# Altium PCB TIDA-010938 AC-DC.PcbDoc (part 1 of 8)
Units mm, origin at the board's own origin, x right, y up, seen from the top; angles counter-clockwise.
Board outline 280 x 180.15 mm, 4 copper layers (Top Layer, Layer 1, Layer 2, Bottom Layer), stack 1.787 mm thick; 723 components, 427 nets, 2244 pads, 2295 vias.
Unrouted connection lines stored in the file: 17.
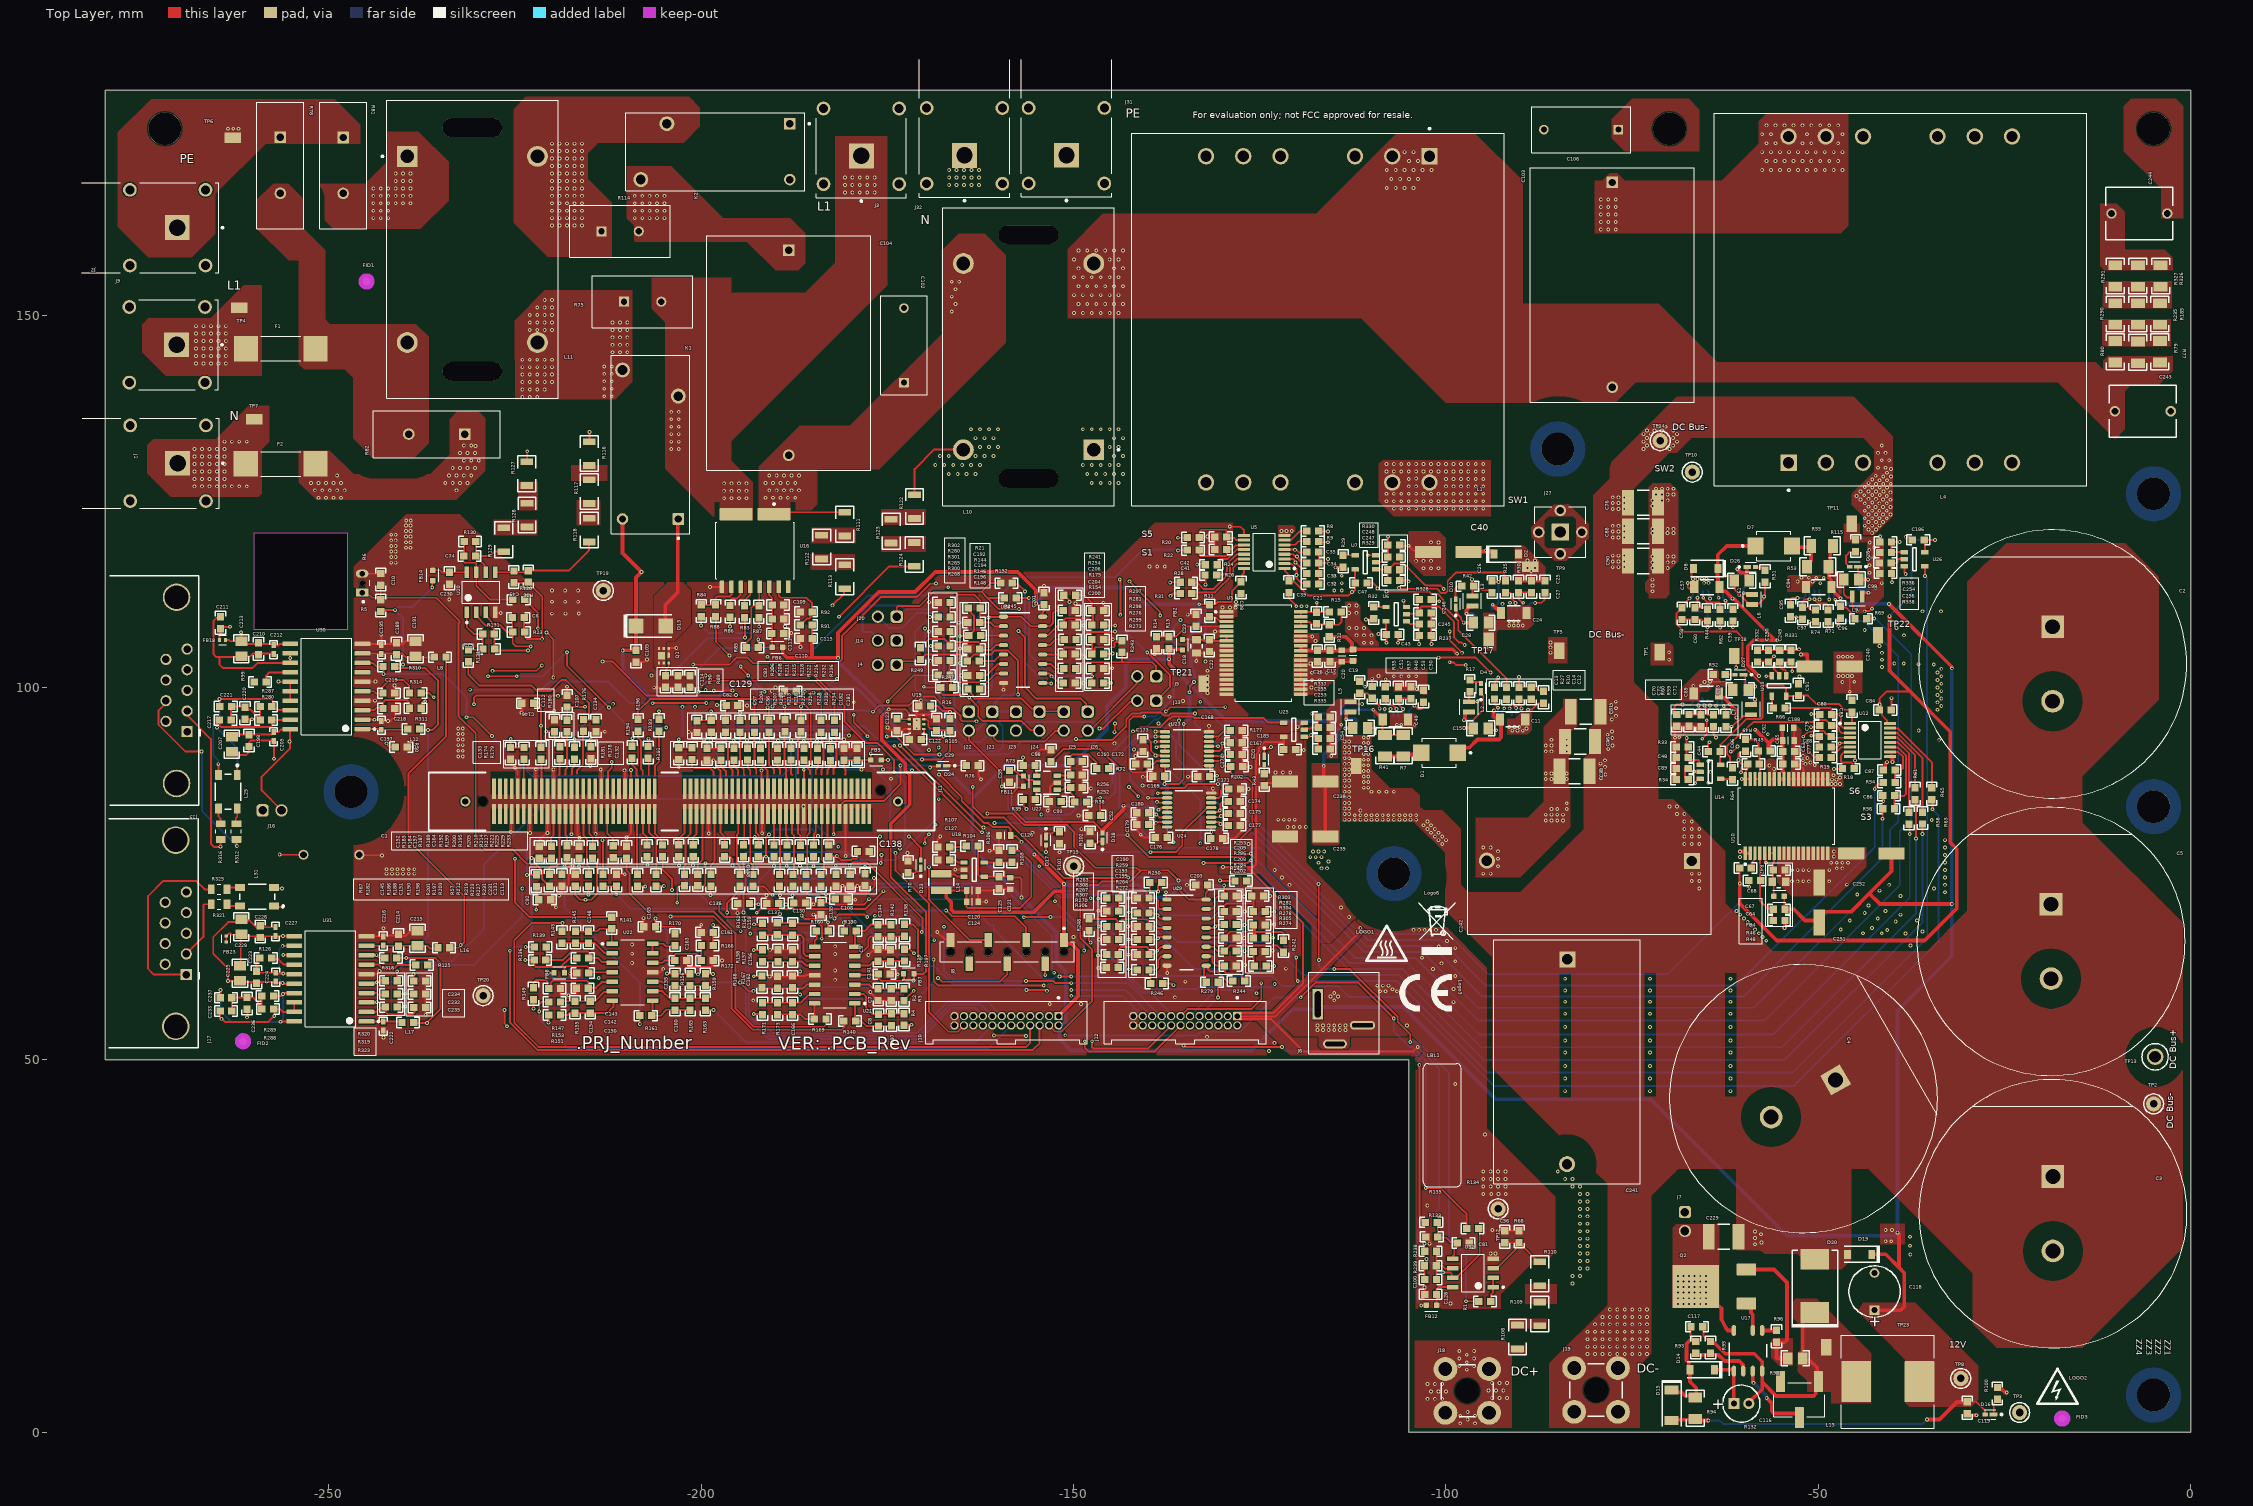
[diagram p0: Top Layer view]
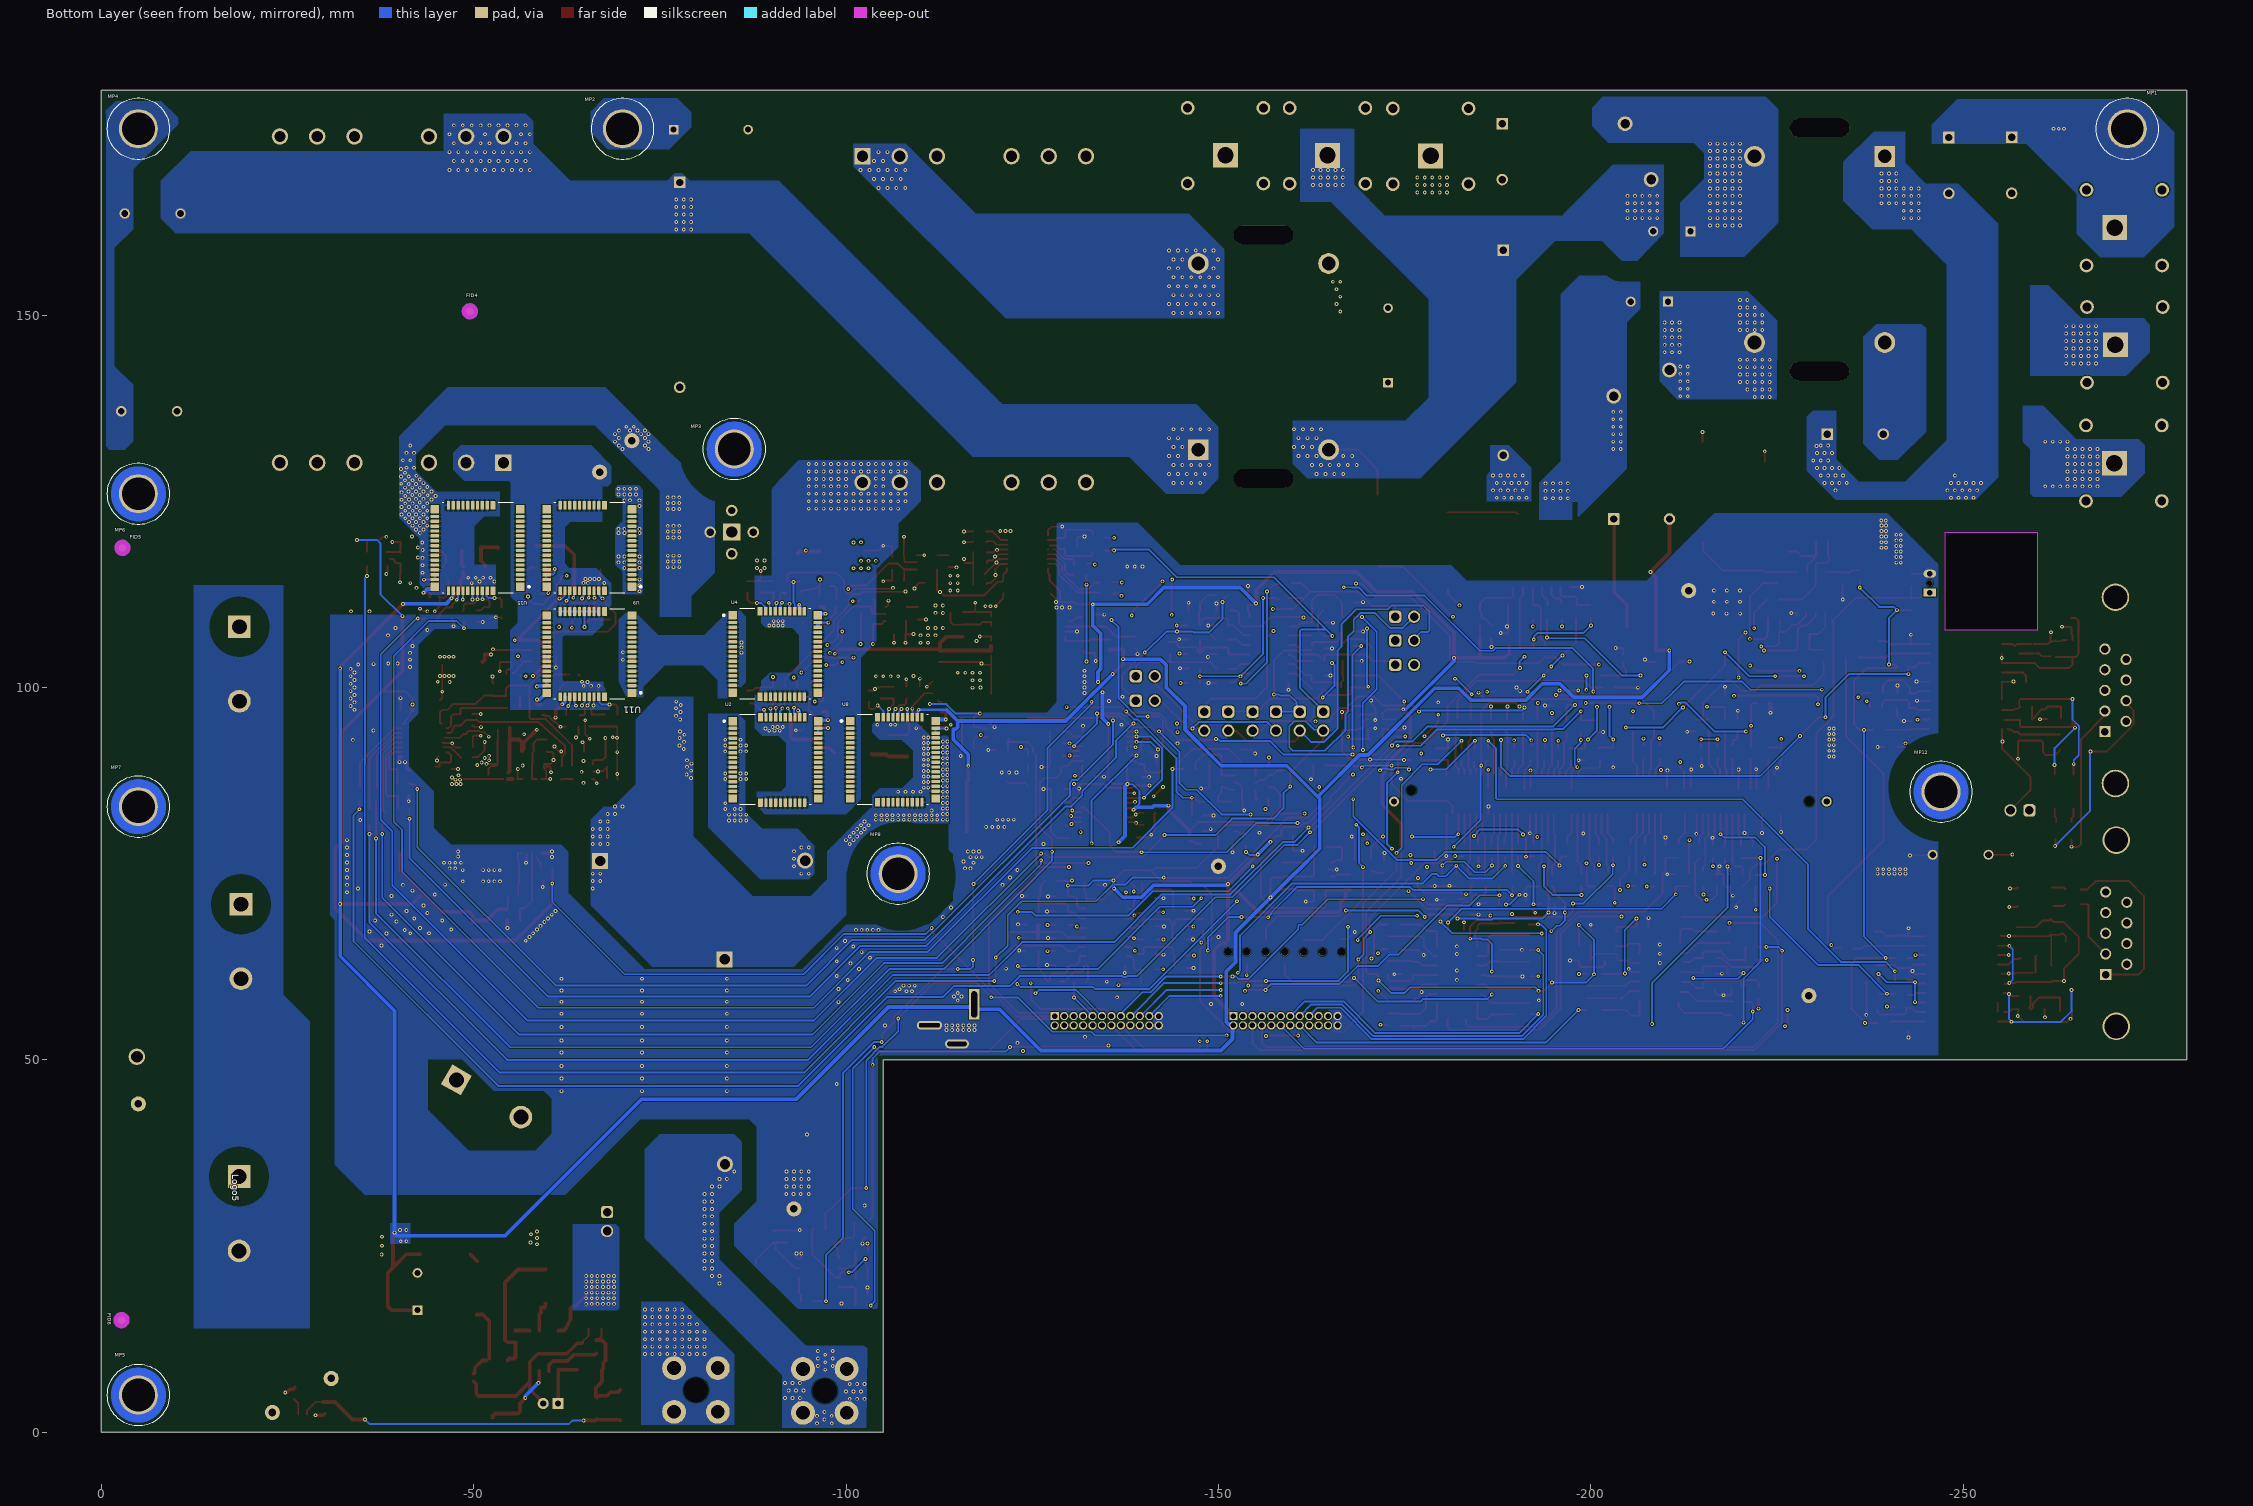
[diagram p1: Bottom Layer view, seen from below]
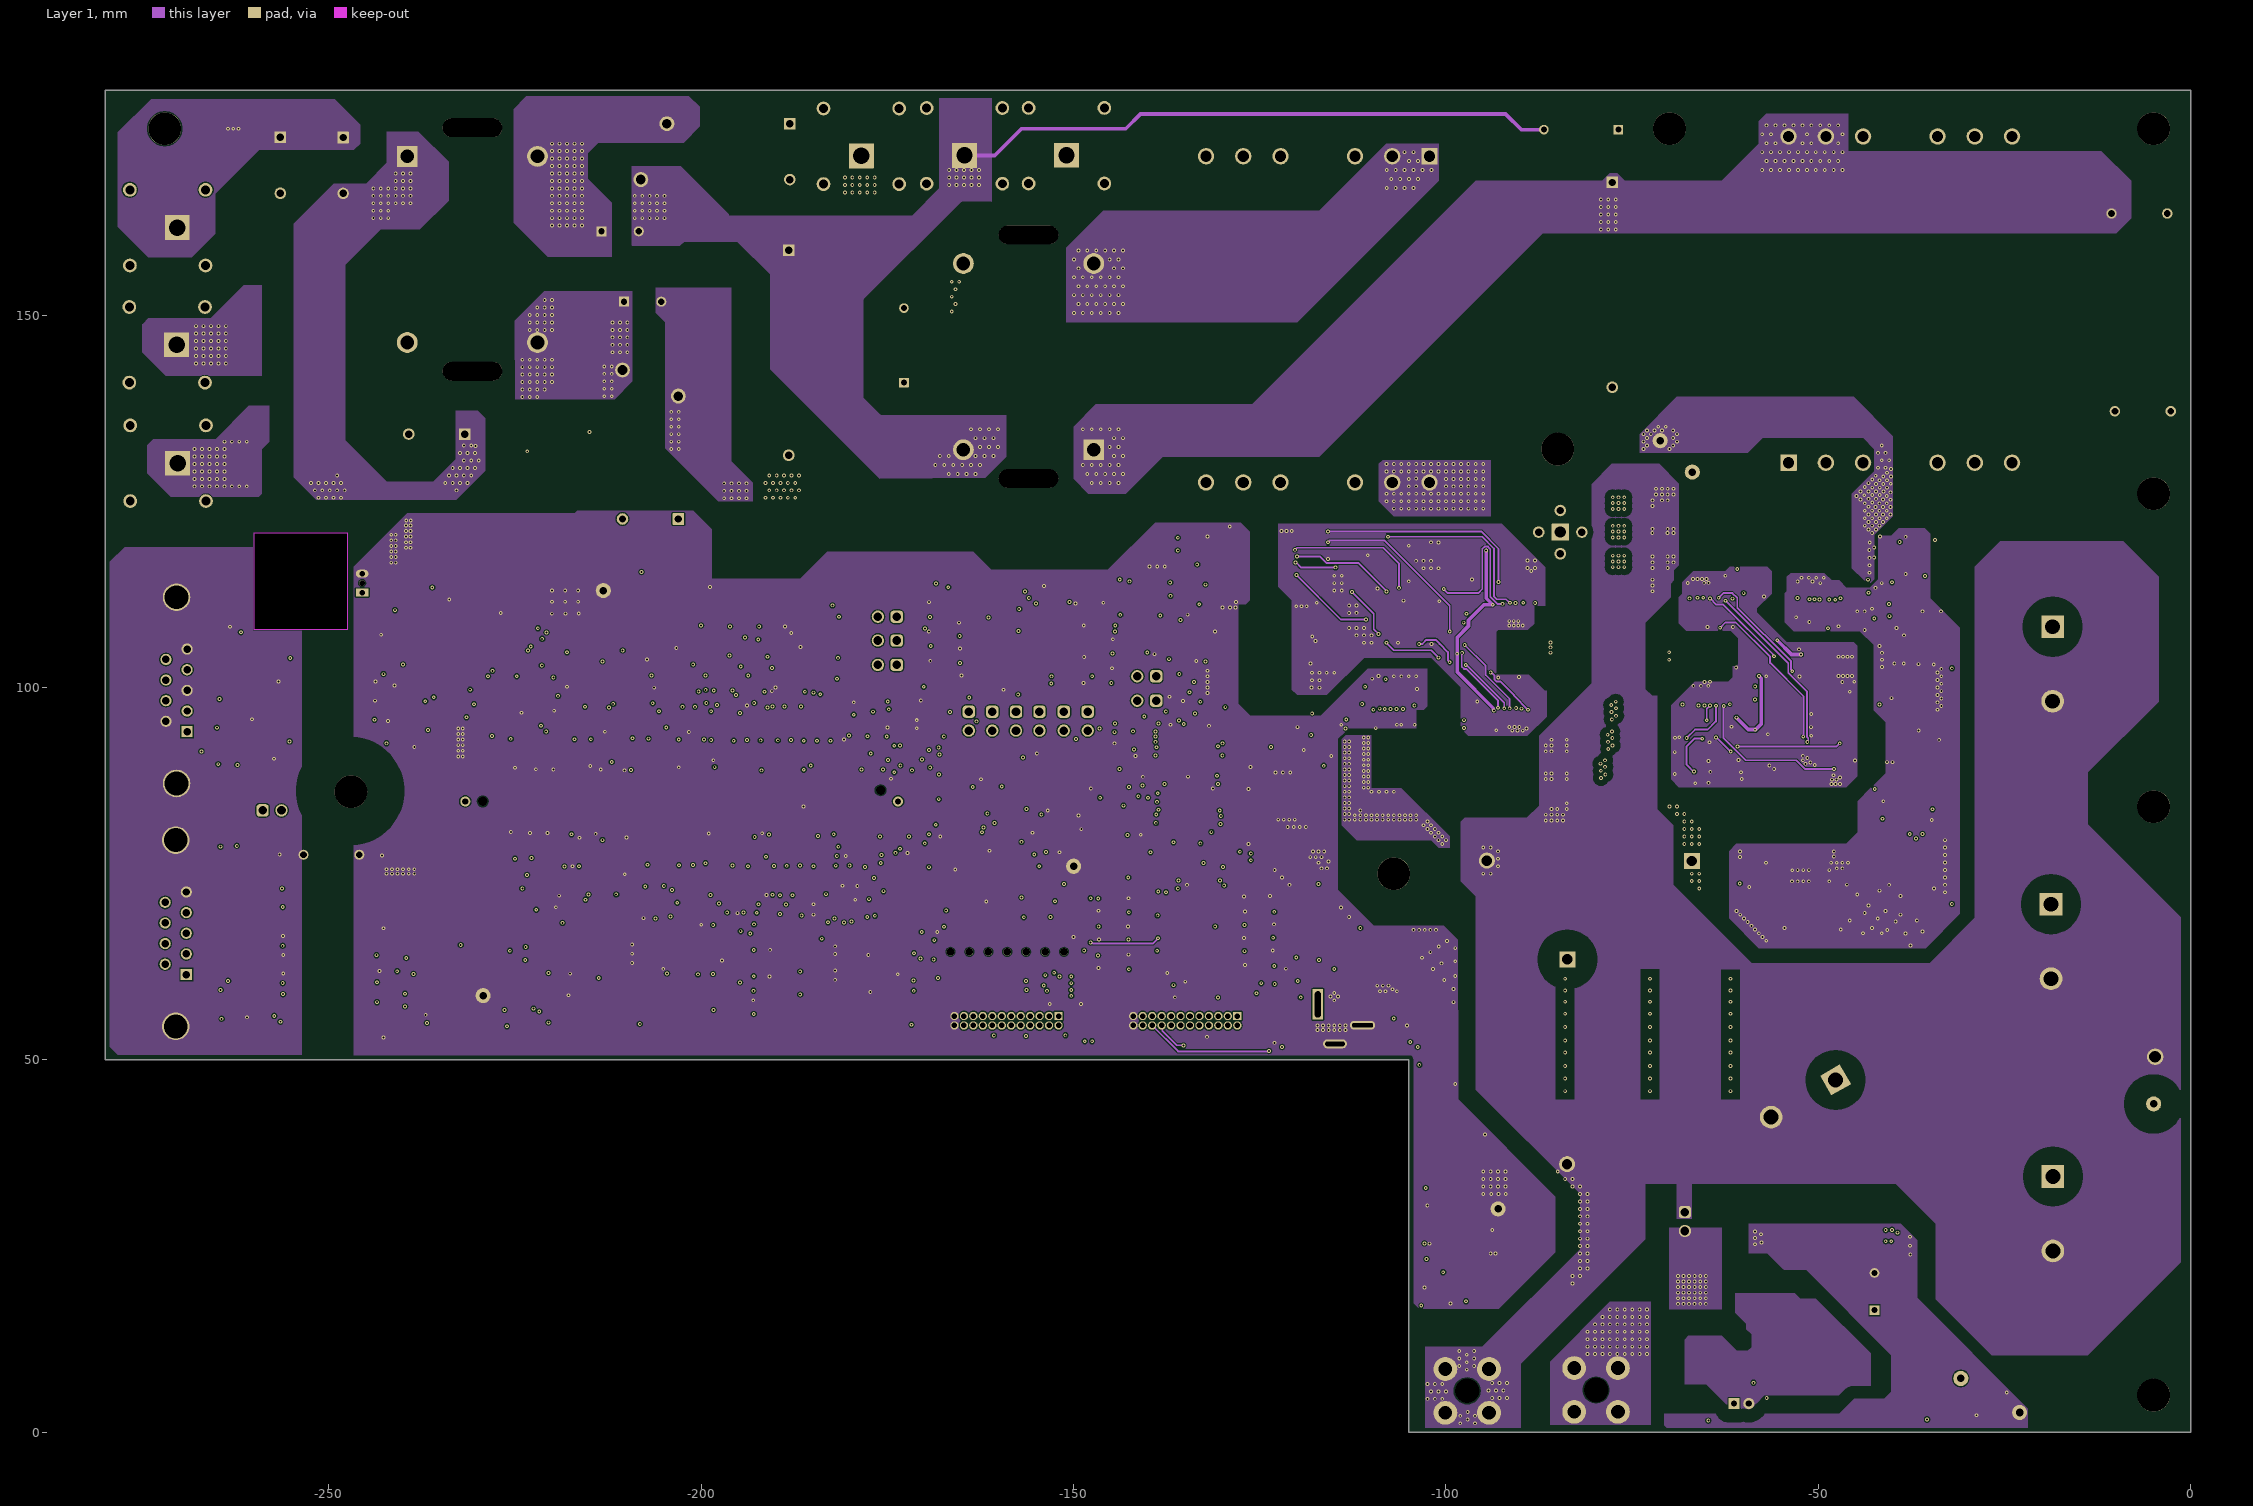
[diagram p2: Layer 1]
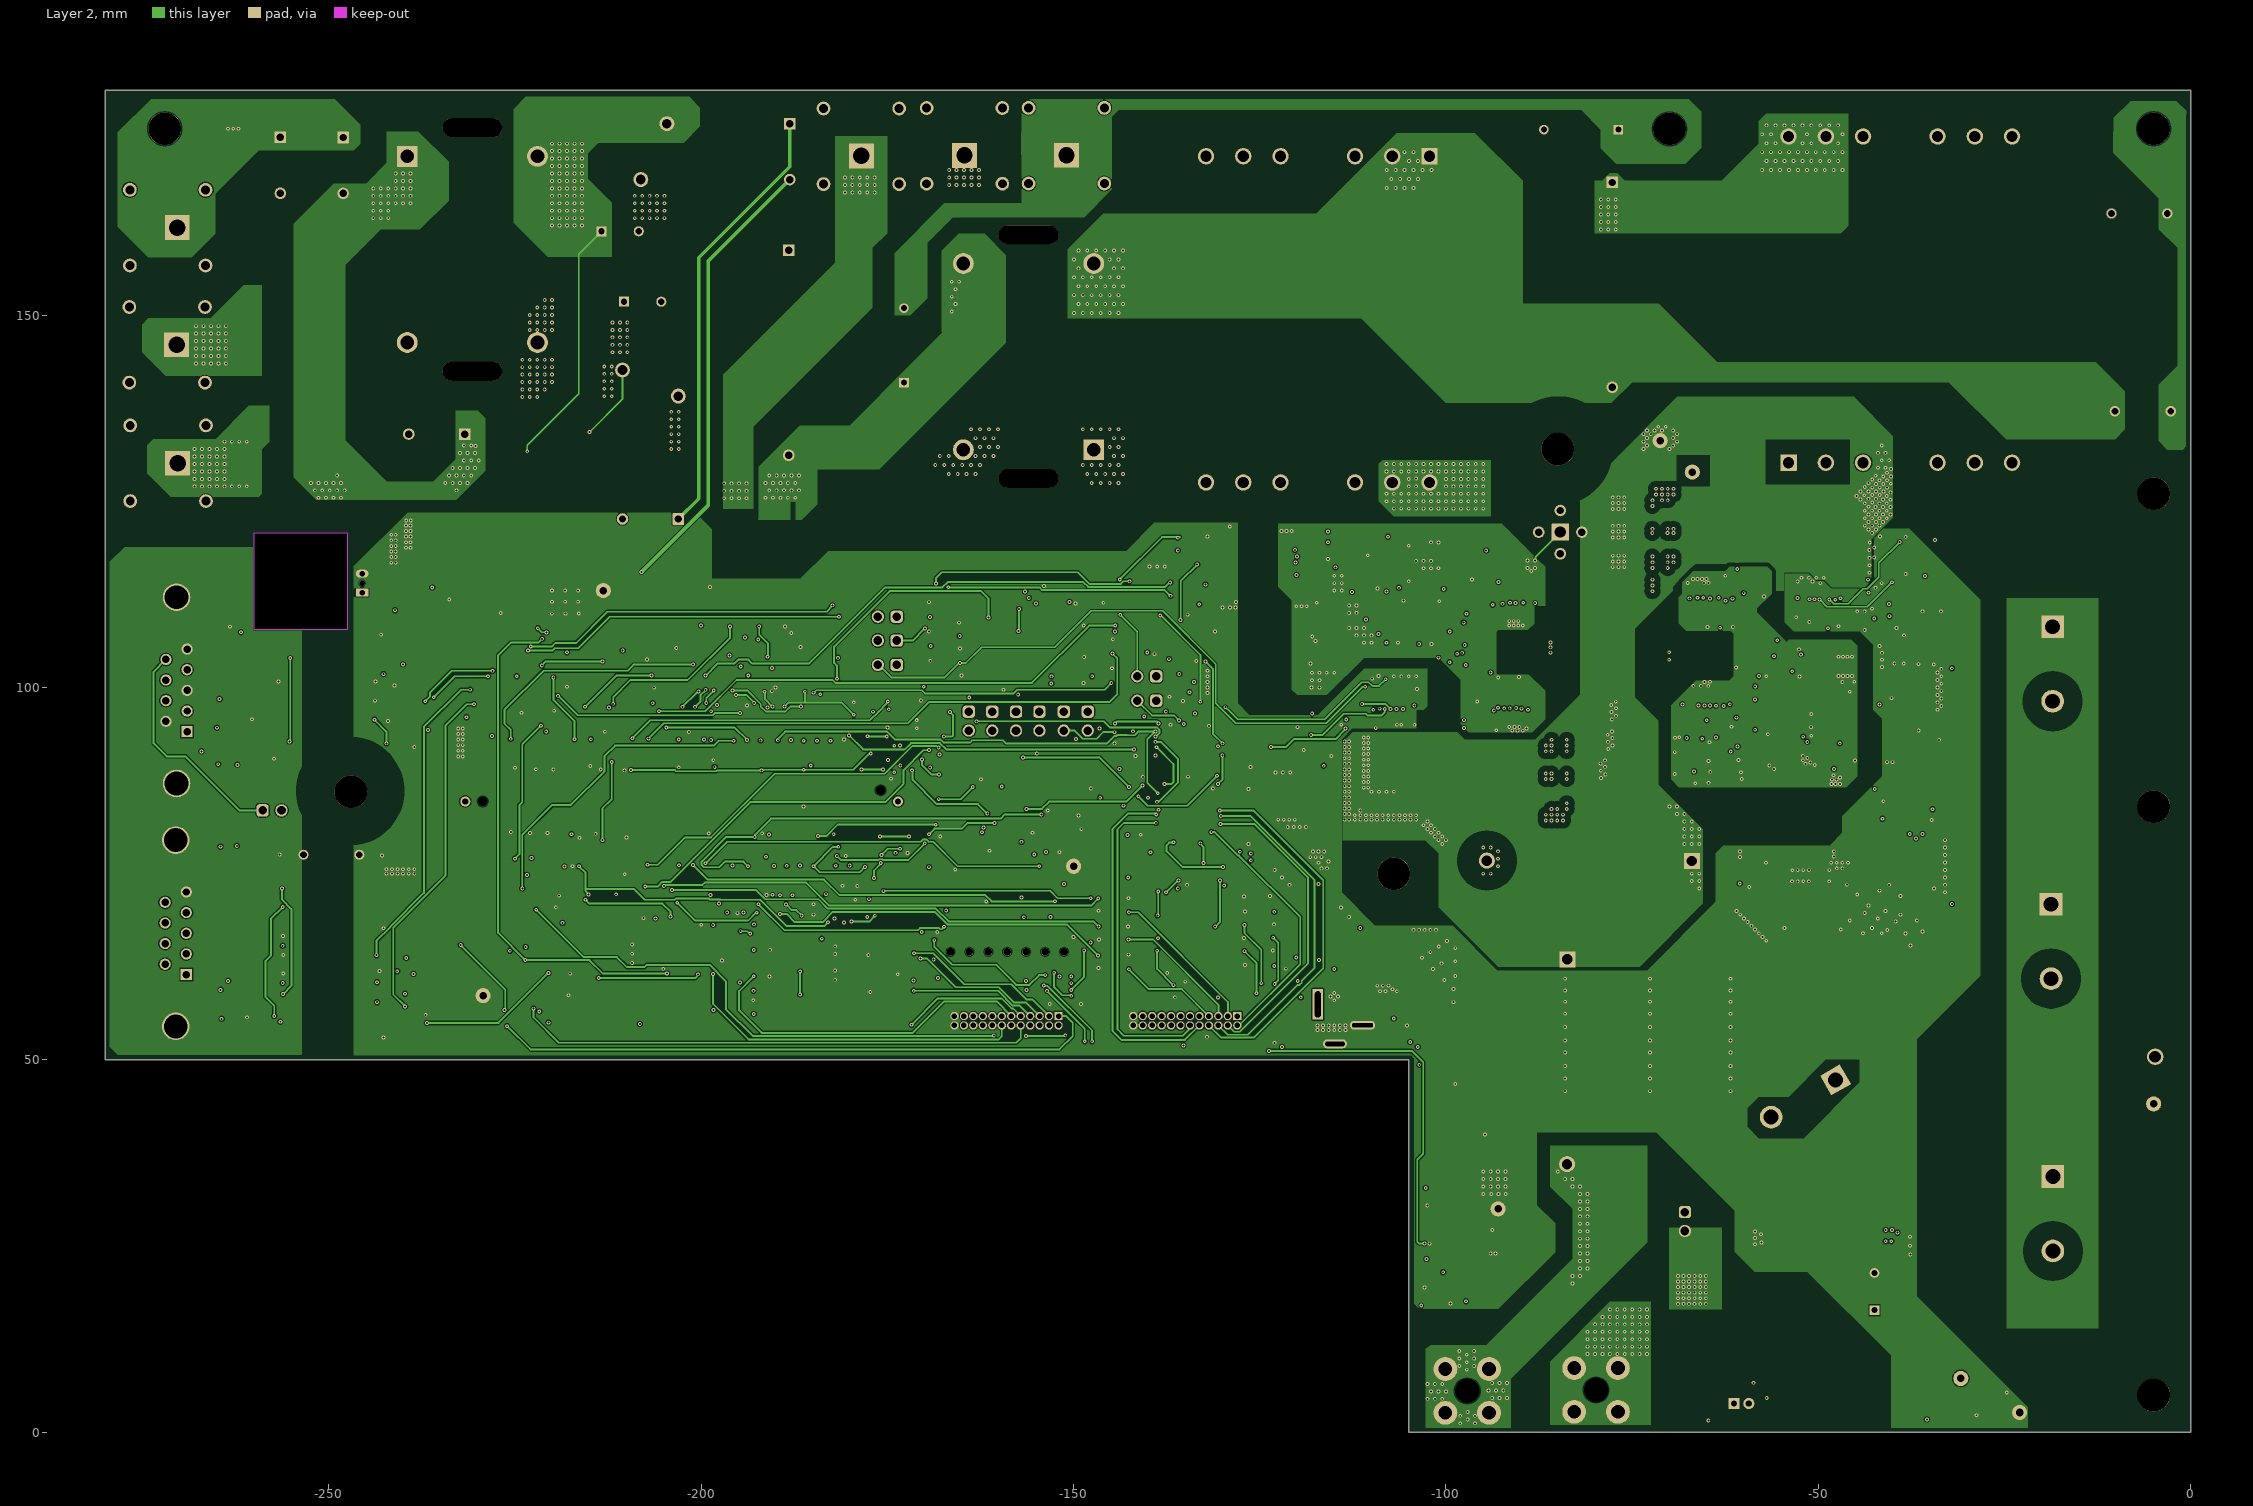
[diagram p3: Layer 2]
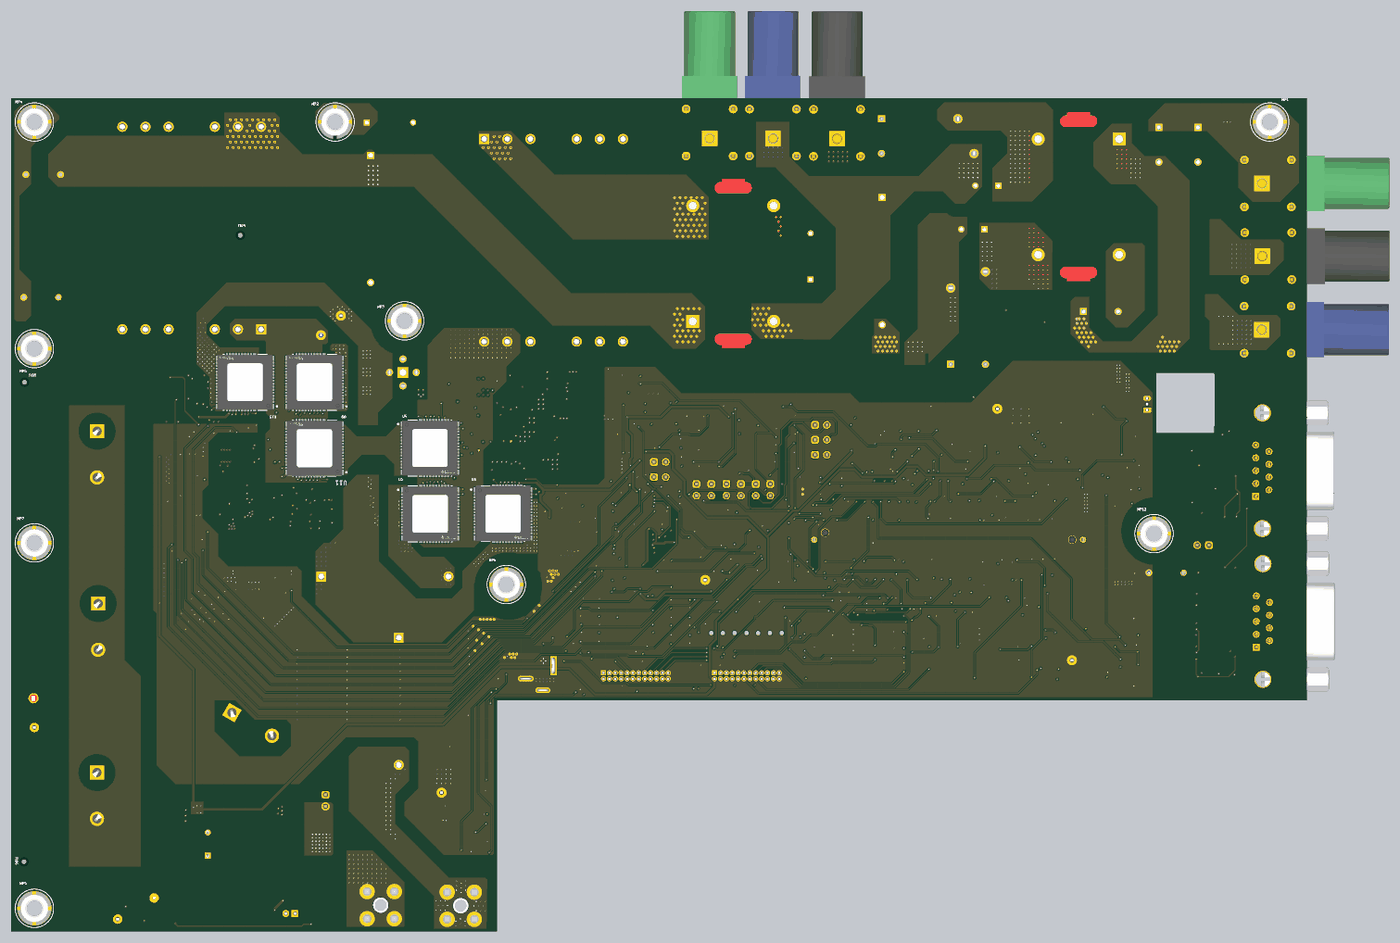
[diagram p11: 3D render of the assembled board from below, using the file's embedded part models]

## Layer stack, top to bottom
Top Solder: solder mask 0.0102, Solder Resist, Dk 3.5
Top Layer: signal copper 0.0356
Dielectric 1: prepreg 0.0711, PP-006, Dk 4.1
Layer 1: signal copper 0.035
Dielectric1: core 1.5037, FR-4 High Tg, Dk 4.8
Layer 2: signal copper 0.035
Dielectric 2: prepreg 0.0711, PP-006, Dk 4.1
Bottom Layer: signal copper 0.0356
Bottom Solder: solder mask 0.0102, Solder Resist, Dk 3.5

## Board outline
-105,0 0,0 0,180.15 -280,180.15 -280,50 -105,50
cut-out: -247.5,120.75 -247.5,107.75 -260,107.75 -260,120.75

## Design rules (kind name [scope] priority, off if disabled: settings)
AcuteAngle [All] p1: minimum=4.50000000000000E+0001 checktracksonly=FALSE
AssemblyTestPointUsage [All] p1: valid=2
BoardOutlineClearance BoardOutlineClearance_MountingHoles [OnCopper and InComponentClass('Mounting Holes')] p1: gap=1 ignorepadtopadclearanceinfootprint=FALSE
BoardOutlineClearance BoardOutlineClearance_Poly [OnCopper and IsPoly] p2: gap=0.635 ignorepadtopadclearanceinfootprint=FALSE
BoardOutlineClearance [OnCopper and Not InComponentClass('Logo') and not InComponentClass('FiducialMark') and not InRegion(1000,500,4000,800) and not InPoly] p3: gap=1.016 ignorepadtopadclearanceinfootprint=FALSE
Clearance PE_PELV [InNetClass('PE') vs InNetClass('PELV')] p1: gap=2 ignorepadtopadclearanceinfootprint=FALSE
Clearance BUCK [InNetClass('HVP')   OR InNetClass('HVN') vs InNetClass('Buck')] p2: gap=1.8 ignorepadtopadclearanceinfootprint=FALSE
Clearance SW1 [(InNetClass('HVN')) OR (InNetClass('HVP')) vs InNetClass('HV_SW_Node1')] p3: gap=0.6 ignorepadtopadclearanceinfootprint=FALSE
Clearance SW2 [(InNetClass('HVN')) OR (InNetClass('HVP')) vs InNetClass('HV_SW_Node2')] p4: gap=0.6 ignorepadtopadclearanceinfootprint=FALSE
Clearance SWMID [((InNetClass('HV_SW_Node1')) OR (InNetClass('HV_SW_Node2'))) vs InNetClass('HV_SW_Mid')] p5: gap=2.1 ignorepadtopadclearanceinfootprint=FALSE
Clearance ACL_ACN [InNetClass('ACL') vs InNetClass('ACN')] p6: gap=2.8 ignorepadtopadclearanceinfootprint=FALSE
Clearance PE [InNetClass('PE') vs InNetClass('All Nets')] p7 off: gap=2.5 ignorepadtopadclearanceinfootprint=FALSE
Clearance PELV [InNetClass('PELV')] p8 off: gap=6 ignorepadtopadclearanceinfootprint=FALSE
Clearance HVN_HVP [InNetClass('HVN') vs InNetClass('HVP')] p9: gap=0.8 ignorepadtopadclearanceinfootprint=FALSE
Clearance Minimum_Distance [All] p10: gap=0.15 ignorepadtopadclearanceinfootprint=FALSE
Clearance Clearance_Keepouts [((IsTrack Or IsArc) And Not InPoly) And IsFree and IsKeepOut vs ((IsTrack Or IsArc) And Not InPoly) And IsFree and IsKeepOut] p11 off: gap=0 ignorepadtopadclearanceinfootprint=FALSE
Clearance Clearance_Poly [InPolygon] p12: gap=0.254 ignorepadtopadclearanceinfootprint=TRUE
Clearance Clearance_FiducialMark [IsKeepOut and InComponentClass('FiducialMark') vs IsPad and InComponentClass('FiducialMark')] p13: gap=0 ignorepadtopadclearanceinfootprint=FALSE
ComponentClearance ComponentClearance_MountingHoles_FiducialMarks [InComponentClass('Mounting Holes') vs InComponentClass('FiducialMark')] p1: gap=1.27 collisioncheckmode=3 verticalgap=0.254 showdistances=FALSE
ComponentClearance ComponentClearance_Shunt [InComponentClass('Header') vs InComponentClass('Shunt')] p2: gap=0 collisioncheckmode=3 verticalgap=0 showdistances=FALSE
ComponentClearance ComponentClearance_Logo [InComponentClass('Logo')] p3: gap=0.762 collisioncheckmode=3 verticalgap=0.254 showdistances=FALSE
ComponentClearance ComponentClearance_ScrewToNut [(HasFootprint('NY PMS 440 0025 PH')) vs (HasFootprint('Keystone_1902C'))] p4: gap=0.127 collisioncheckmode=3 verticalgap=0.254 showdistances=FALSE
ComponentClearance ComponentClearance_MountingHoles [InComponentClass('Mounting Holes')] p5: gap=2.54 collisioncheckmode=3 verticalgap=2540 showdistances=FALSE
ComponentClearance ComponentClearance_SmallPassives [HasFootprint('0201*') or HasFootprint('0402*') or HasFootprint('0508') or HasFootprint('0603*') or HasFootprint('0612') or HasFootprint('0805*') or HasFootprint('0815*') or HasFootprint('0830*') or HasFootprint('1206*') or HasFootprint('1210*') or HasFootprint('1808*') or HasFootprint('1812*') or HasFootprint('1825*') or HasFootprint('2010*') or HasFootprint('2220*') or HasFootprint('2225*') or HasFootprint('2512*') or HasFootprint('2728*') or HasFootprint('3518*') vs HasFootprint('0201*') or HasFootprint('0402*') or HasFootprint('0508') or HasFootprint('0603*') or HasFootprint('0612') or HasFootprint('0805*') or HasFootprint('0815*') or HasFootprint('0830*') or HasFootprint('1206*') or HasFootprint('1210*') or HasFootprint('1808*') or HasFootprint('1812*') or HasFootprint('1825*') or HasFootprint('2010*') or HasFootprint('2220*') or HasFootprint('2225*') or HasFootprint('2512*') or HasFootprint('2728*') or HasFootprint('3518*')] p6: gap=0.38 collisioncheckmode=3 verticalgap=0.254 showdistances=FALSE
ComponentClearance ComponentClearance_THtoSMT [IsThruComponent vs IsSMTComponent] p7: gap=0.762 collisioncheckmode=3 verticalgap=0.762 showdistances=FALSE
ComponentClearance ComponentClearance_THtoTH [IsThruComponent vs IsThruComponent] p8: gap=0.508 collisioncheckmode=3 verticalgap=0.762 showdistances=FALSE
ComponentClearance [All] p9: gap=0.508 collisioncheckmode=3 verticalgap=0.254 showdistances=FALSE
DiffPairsRouting [All] p1: maxlimit=2.54 minlimit=0.254 mostfreqgap=0.254 toplayer_minwidth=0.381 toplayer_maxwidth=0.381 toplayer_prefwidth=0.381 midlayer1_minwidth=0.381 midlayer1_maxwidth=0.381 midlayer1_prefwidth=0.381 midlayer2_minwidth=0.381 midlayer2_maxwidth=0.381 midlayer2_prefwidth=0.381 bottomlayer_minwidth=0.381 bottomlayer_maxwidth=0.381 bottomlayer_prefwidth=0.381 maxuncoupledlength=25.4
FabricationTestPointUsage TestPointUsage [All] p1: valid=2 allowmultiple=FALSE
FabricationTestpoint Testpoint [All] p1: side=3 testpointundercomponent=TRUE minsize=1.016 maxsize=2.54 preferedsize=1.524 minholesize=0 maxholesize=1.016 preferedholesize=0.813 testpointgrid=0.025 allowsidetop=TRUE allowsidebottom=TRUE usegrid=TRUE gridtolerance=0
FanoutControl Fanout_LCC [IsLCC] p1: bgadir=Out bgaviamode=Centered fanoutstyle=Auto fanoutdirection=Alternating viagrid=0.025 // Fanout_LCC (Default Rule)
FanoutControl Fanout_BGA [IsBGA] p2: bgadir=Out bgaviamode=Centered fanoutstyle=Auto fanoutdirection=Alternating viagrid=0.025 // Fanout_BGA (Default Rule)
FanoutControl Fanout_Default [All] p4: bgadir=Out bgaviamode=Centered fanoutstyle=Auto fanoutdirection=Alternating viagrid=0.025 // Fanout_Default (Default Rule)
FanoutControl Fanout_Small [(CompPinCount < 5)] p5: bgadir=Out bgaviamode=Centered fanoutstyle=Auto fanoutdirection=OutThenIn viagrid=0.025 // Fanout_Small (Default Rule)
HoleSize [All] p1: absolutevalues=TRUE maxlimit=6.375 minlimit=0.2 maxpercent=80.000 minpercent=20.000
MinimumAnnularRing MinimumAnnularRing_ThermalPadVias [IsVia and InAnyComponent] p1: minimumring=0.125
MinimumAnnularRing [All] p2: minimumring=0.125
MinimumSolderMaskSliver MinimumSolderMaskSliver_Logo [InComponentClass('Logo') vs InComponentClass('Logo')] p1: minsoldermaskwidth=0.018
MinimumSolderMaskSliver [All] p2: minsoldermaskwidth=0.1
PlaneConnect [All] p1: planeconnectstyle=Relief reliefexpansion=0.254 reliefentries=4 reliefconductorwidth=0.254 reliefairgap=0.254
PolygonConnect "GaN 1" [IsNamedPolygon('Bottom Layer-DC Bus-')] p1: thpad.connectstyle=Direct thpad.reliefconductorwidth=0.254 thpad.reliefentries=4 thpad.polygonreliefangle="90 Angle" thpad.airgapwidth=0.254 smdpad.connectstyle=Relief smdpad.reliefconductorwidth=0.254 smdpad.reliefentries=4 smdpad.polygonreliefangle="90 Angle" smdpad.airgapwidth=0.254 via.connectstyle=Direct via.reliefconductorwidth=0.254 via.reliefentries=4 via.polygonreliefangle="90 Angle" via.airgapwidth=0.254
PolygonConnect "GaN 2" [IsNamedPolygon('Bottom Layer-SW_2')] p2: thpad.connectstyle=Direct thpad.reliefconductorwidth=0.254 thpad.reliefentries=4 thpad.polygonreliefangle="90 Angle" thpad.airgapwidth=0.254 smdpad.connectstyle=Relief smdpad.reliefconductorwidth=0.254 smdpad.reliefentries=4 smdpad.polygonreliefangle="90 Angle" smdpad.airgapwidth=0.254 via.connectstyle=Direct via.reliefconductorwidth=0.254 via.reliefentries=4 via.polygonreliefangle="90 Angle" via.airgapwidth=0.254
PolygonConnect "GaN 3" [IsNamedPolygon('BOTTOM_LAYER_SW_MID_P059')] p3: thpad.connectstyle=Direct thpad.reliefconductorwidth=0.254 thpad.reliefentries=4 thpad.polygonreliefangle="90 Angle" thpad.airgapwidth=0.254 smdpad.connectstyle=Relief smdpad.reliefconductorwidth=0.254 smdpad.reliefentries=4 smdpad.polygonreliefangle="90 Angle" smdpad.airgapwidth=0.254 via.connectstyle=Direct via.reliefconductorwidth=0.254 via.reliefentries=4 via.polygonreliefangle="90 Angle" via.airgapwidth=0.254
PolygonConnect "GaN 4" [IsNamedPolygon('BOTTOM_LAYER_DC_BUS+_P066')] p4: thpad.connectstyle=Direct thpad.reliefconductorwidth=0.254 thpad.reliefentries=4 thpad.polygonreliefangle="90 Angle" thpad.airgapwidth=0.254 smdpad.connectstyle=Relief smdpad.reliefconductorwidth=0.254 smdpad.reliefentries=4 smdpad.polygonreliefangle="90 Angle" smdpad.airgapwidth=0.254 via.connectstyle=Direct via.reliefconductorwidth=0.254 via.reliefentries=4 via.polygonreliefangle="90 Angle" via.airgapwidth=0.254
PolygonConnect "GaN 5" [IsNamedPolygon('Bottom Layer-SW_1')] p5: thpad.connectstyle=Direct thpad.reliefconductorwidth=0.254 thpad.reliefentries=4 thpad.polygonreliefangle="90 Angle" thpad.airgapwidth=0.254 smdpad.connectstyle=Relief smdpad.reliefconductorwidth=0.254 smdpad.reliefentries=4 smdpad.polygonreliefangle="90 Angle" smdpad.airgapwidth=0.254 via.connectstyle=Direct via.reliefconductorwidth=0.254 via.reliefentries=4 via.polygonreliefangle="90 Angle" via.airgapwidth=0.254
PolygonConnect "GaN 6" [IsNamedPolygon('BOTTOM_LAYER_DC_BUS+_P007')] p6: thpad.connectstyle=Direct thpad.reliefconductorwidth=0.254 thpad.reliefentries=4 thpad.polygonreliefangle="90 Angle" thpad.airgapwidth=0.254 smdpad.connectstyle=Relief smdpad.reliefconductorwidth=0.254 smdpad.reliefentries=4 smdpad.polygonreliefangle="90 Angle" smdpad.airgapwidth=0.254 via.connectstyle=Direct via.reliefconductorwidth=0.254 via.reliefentries=4 via.polygonreliefangle="90 Angle" via.airgapwidth=0.254
PolygonConnect "GaN 7" [IsNamedPolygon('BOTTOM_LAYER_DC_BUS-_P082')] p7: thpad.connectstyle=Direct thpad.reliefconductorwidth=0.254 thpad.reliefentries=4 thpad.polygonreliefangle="90 Angle" thpad.airgapwidth=0.254 smdpad.connectstyle=Relief smdpad.reliefconductorwidth=0.254 smdpad.reliefentries=4 smdpad.polygonreliefangle="90 Angle" smdpad.airgapwidth=0.254 via.connectstyle=Direct via.reliefconductorwidth=0.254 via.reliefentries=4 via.polygonreliefangle="90 Angle" via.airgapwidth=0.254
PolygonConnect [All] p8: connectstyle=Direct reliefconductorwidth=0.254 reliefentries=4 polygonreliefangle="90 Angle" airgapwidth=0.254
RoutingVias ThermalPadVias [IsVia and InAnyComponent] p1: holewidth=0.254 width=0.508 viastyle="Through Hole" minholewidth=0.2 minwidth=0.5 maxholewidth=1.016 maxwidth=1.651
RoutingVias [All] p2: holewidth=0.254 width=0.508 viastyle="Through Hole" minholewidth=0.2 minwidth=0.5 maxholewidth=1.016 maxwidth=1.651
SilkToBoardRegionClearance [Not ((IsComment or IsDesignator) And (Hide <> 'False')) and not InRegion(1000,500,4000,800)] p1:
SilkToSilkClearance SilkToSilkClearance_Pb-FreeLogo [(HasFootprint('Pb-Free_Overlay_Medium') OR HasFootprint('Pb-Free_Overlay_Small')) vs (HasFootprint('Pb-Free_Overlay_Medium') OR HasFootprint('Pb-Free_Overlay_Small'))] p1: silktosilkclearance=0
SilkToSilkClearance [All] p2: silktosilkclearance=0.1
SilkToSolderMaskClearance SilkToComponentPadClearance [(IsPad or IsFill or IsRegion) and InAnycomponent] p1: minsilkscreentomaskgap=0.127 clearancetoexposedcopper=TRUE
SilkToSolderMaskClearance "Silk to Solder Mask Opening" [All] p2: minsilkscreentomaskgap=0.1 clearancetoexposedcopper=FALSE
SolderMaskExpansion [All] p1: expansion=0.05 istentingtop=FALSE
UnRoutedNet [All] p1: checkbadconnections=TRUE
Width [All] p1: maxlimit=2.54 minlimit=0.25 preferedwidth=0.5 checkconnectedcopper=TRUE
14 further rules are at their usual default settings.

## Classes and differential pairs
net class LOADN: ACLOAD_N
net class LOADL: ACLOAD_L
net class HVP: "DC Bus+" NetC229_1
net class HV_SW_Mid: SW_mid
net class PE: PE PE2 PE3
net class ACN: AC_N ACLOAD_N NetC103_1 NetF2_1 VAC_N
net class ACL: AC_L ACLOAD_L NetC103_2 NetF1_1 VAC_L VAC_SW+
net class Buck: NetC116_1 NetC116_2 NetC117_1 NetQ2_1 NetQ2_3 NetR93_1 NetR96_1 NetR132_2 NetU17_3
net class HVN: 1V65_REF 3V3_HVN 5V_HVN 12V_HVN Batt_H1 Batt_H1_Buff Batt_H2 Batt_H2_Buff Batt_L1 Batt_L1_Buff Batt_L2 Batt_L2_Buff Boost_S1 Boost_S1_Buff Boost_S2 Boost_S2_Buff CAN_RX CAN_TX CS_Batt1 CS_Batt1+ CS_Batt1- CS_Batt2 CS_Batt2+ CS_Batt2- CS_Boost1 CS_Boost1+ CS_Boost1- CS_Boost2 CS_Boost2+ CS_Boost2- "DC Bus-" Enable_Buffer_ACDC Enable_Buffer_DCDC Enable_CAN Enable_RS485 F\A\U\L\T\_O\C\_Batt_H1_Buff F\A\U\L\T\_O\C\_Batt_H2_Buff F\A\U\L\T\_O\C\_Batt_L1_Buff F\A\U\L\T\_O\C\_Batt_L2_Buff F\A\U\L\T\_O\C\_Boost1_Buff F\A\U\L\T\_O\C\_Boost2_Buff F\A\U\L\T\_O\C\_S1 F\A\U\L\T\_O\C\_S2_init F\A\U\L\T\_O\C\_S3 F\A\U\L\T\_O\C\_S4_init F\A\U\L\T\_O\C\_S5 F\A\U\L\T\_O\C\_S6 F\A\U\L\T\_S2_init F\A\U\L\T\_S4_init IAC_F\A\U\L\T\ IAC_O\C\ IAC_REF IAC_sense NetC6_1 NetC7_2 NetC8_1 NetC8_2 NetC9_2 NetC18_2 NetC23_2 NetC29_2 NetC41_2 NetC42_2 NetC45_1 NetC50_2 NetC51_2 NetC53_2 NetC54_1 NetC55_2 NetC56_2 NetC64_2 NetC68_2 NetC74_1 NetC74_2 NetC75_1 NetC75_2 NetC81_1 NetC86_2 NetC87_2 NetC93_2 NetC95_2 NetC96_2 NetC97_2 NetC99_1 NetC100_1 NetC100_2 NetC101_2 NetC109_1 NetC114_1 NetC127_2 NetC128_2 NetC141_2 NetC142_2 NetC143_2 NetC144_1 NetC144_2 NetC148_1 NetC148_2 NetC150_1 NetC154_1 NetC154_2 NetC155_2 NetC156_1 NetC159_1 NetC159_2 NetC160_1 NetC160_2 NetC162_1 NetC163_2 NetC166_1 NetC166_2 NetC181_2 NetC189_2 NetC190_2 NetC192_2 NetC193_2 NetC194_2 NetC196_2 NetC197_1 NetC199_2 NetC200_2 NetC202_2 NetC204_2 NetC206_2 NetC208_2 NetC209_2 NetC214_2 NetC218_2 NetC219_2 NetC222_1 NetC230_2 NetC234_2 NetC235_2 NetD1_2 NetD7_2 NetD16_1 NetD17_1 NetD18_1 NetD23_1 NetD23_2 NetD24_1 NetD24_2 NetD25_2 NetD28_2 NetH1_1 NetH2_1 NetH3_1 NetH4_1 NetH9_1 NetH10_1 NetH11_1 NetH12_1 NetJ4_1 NetJ5_1 NetJ8_2 NetJ8_3 NetJ8_4 NetJ8_5 NetJ10_16 NetJ10_18 NetJ10_20 NetJ10_22 NetJ11_1 NetJ11_2 NetJ11_3 NetJ11_4 NetJ11_5 NetJ11_6 NetJ11_8 NetJ11_9 NetJ11_11 NetJ11_12 NetJ11_18 NetJ11_20 NetJ11_21 NetJ11_23 NetJ11_24 NetJ11_25 NetJ11_26 NetJ11_27 NetJ11_28 NetJ11_30 NetJ11_31 NetJ11_32 NetJ11_33 NetJ11_34 NetJ11_36 NetJ11_39 NetJ11_40 NetJ11_41 NetJ11_42 NetJ11_43 NetJ11_44 NetJ11_45 NetJ11_49 NetJ11_50 NetJ11_51 NetJ11_52 NetJ11_53 NetJ11_54 NetJ11_55 NetJ11_56 NetJ11_57 NetJ11_58 NetJ11_59 NetJ11_60 NetJ11_61 NetJ11_62 NetJ11_63 NetJ11_64 NetJ11_66 NetJ11_67 NetJ11_68 NetJ11_69 NetJ11_70 NetJ11_71 NetJ11_72 NetJ11_73 NetJ11_74 NetJ11_75 NetJ11_76 NetJ11_77 NetJ11_78 NetJ11_79 NetJ11_80 NetJ11_81 NetJ11_82 NetJ11_85 NetJ11_86 NetJ11_87 NetJ11_88 NetJ11_89 NetJ11_90 NetJ11_91 NetJ11_92 NetJ11_93 NetJ11_94 NetJ11_95 NetJ11_96 NetJ11_99 NetJ11_100 NetJ11_101 NetJ11_102 NetJ11_103 NetJ11_104 NetJ11_105 NetJ11_106 NetJ11_107 NetJ11_108 NetJ11_109 NetJ11_110 NetJ11_113 NetJ11_114 NetJ11_115 NetJ11_116 NetJ11_117 NetJ11_118 NetJ11_120 NetJ12_20 NetJ12_22 NetJ13_1 NetJ14_1 NetJ15_1 NetJ15_8 NetJ17_3 NetJ17_4 NetJ17_6 NetJ17_7 NetJ17_8 NetJ17_9 NetJ20_1 NetL5_2 NetL9_2 NetL14_1 NetR1_1 NetR11_2 NetR24_2 NetR26_2 NetR28_2 NetR31_2 NetR37_2 NetR39_1 NetR47_2 NetR50_1 NetR58_2 NetR61_2 NetR63_2 NetR65_2 NetR71_2 NetR73_1 NetR83_1 NetR84_2 NetR85_2 NetR86_2 NetR91_2 NetR103_2 NetR125_1 NetR144_1 NetR146_1 NetR148_1 NetR152_1 NetR154_1 NetR170_1 NetR175_1 NetR177_2 NetR202_2 NetR240_2 NetR242_2 NetR244_2 NetR246_2 NetR248_2 NetR250_2 NetR319_2 NetU17_3 NetU19_2 NetU19_5 NetU23_6 NetU24_6 NetU30_2 NetU30_7 NetU30_14 NetU31_7 NetU31_14 O\C\_S2_init O\C\_S4_init PWM_S1 PWM_S1_Buff PWM_S2 PWM_S2_Buff PWM_S3 PWM_S3_Buff PWM_S4 PWM_S4_Buff PWM_S5 PWM_S5_Buff PWM_S6 PWM_S6_Buff RS485_D RS485_DE_R\E\ RS485_R RY_DCPreCharge RY_PreCharge SN_Relays_PreCharge TEMP_ACDC TEMP_AMB_sense TEMP_Batt_H1_Buff TEMP_Batt_H2_Buff TEMP_Batt_L1_Buff TEMP_Batt_L2_Buff TEMP_Boost1_Buff TEMP_Boost2_Buff TEMP_DCDC TEMP_MUX_A TEMP_MUX_B TEMP_MUX_C TEMP_S1 TEMP_S2 TEMP_S2_init TEMP_S3 TEMP_S4 TEMP_S4_init TEMP_S5 TEMP_S6 VAC_sense VDC_sense Vinv_sense VS_Batt1 VS_Batt1+ VS_Batt1- VS_Boost1 VS_Boost1+ VS_Boost1- VS_Boost2 VS_Boost2+ VS_Boost2- VS_DCDC_VDC+ VS_DCDC_VDC- VS_DCDC_VDC_sense
net class PELV: GND_ISO_COMM NetC210_1 NetC217_1 NetC217_2 NetC221_1 NetC233_1 NetC233_2 NetC237_1 NetJ15_1 NetJ15_2 NetJ15_7 NetJ15_8 NetJ15_9 NetJ17_1 NetJ17_2 NetJ17_3 NetJ17_4 NetJ17_6 NetJ17_7 NetJ17_8 NetJ17_9 NetL25_3 NetL25_4 NetL31_3 NetL31_4 NetR99_2 NetR126_2 NetU30_14 NetU31_14 VIN_PWR_CAN VP_CAN VP_RS485
net class HV_SW_Node1: 5V_SW1 12V_SW1 F\A\U\L\T\_O\C\_S1_init F\A\U\L\T\_O\C\_S5_init F\A\U\L\T\_S1 F\A\U\L\T\_S5 IN_PWM_S1 IN_PWM_S5 NetC14_2 NetC15_1 NetC21_1 NetC25_2 NetC27_2 NetC28_1 NetC32_2 NetC33_2 NetC34_2 NetC35_2 NetD4_2 NetD10_2 NetL2_2 NetL3_2 NetR8_1 NetR9_1 NetU3_32 O\C\_S1 O\C\_S5 SW_1 TEMP_S1_init TEMP_S5_init
net class HV_SW_Node2: 5V_SW2 12V_SW2 F\A\U\L\T\_O\C\_S3_init F\A\U\L\T\_O\C\_S6_init F\A\U\L\T\_S3 F\A\U\L\T\_S6 IN_PWM_S3 IN_PWM_S6 NetC60_2 NetC61_1 NetC66_1 NetC70_2 NetC72_2 NetC73_1 NetC77_2 NetC78_2 NetC79_2 NetC80_2 NetD26_2 NetD27_2 NetJ15_1 NetJ15_8 NetJ17_3 NetJ17_4 NetJ17_6 NetJ17_7 NetJ17_8 NetJ17_9 NetL6_2 NetL7_2 NetR18_1 NetR19_1 NetU3_32 NetU10_32 NetU30_14 NetU31_14 O\C\_S3 O\C\_S6 SW_2 TEMP_S3_init TEMP_S6_init
component class Designator: C1 C2 C3 C4 C5 C10 C241 C242 J1 J2 J3 J6 J9 J18 J19 J31 J32 R5 R6 TP3 TP20
component class Header: J4 J5 J7 J13 J14 J16 J20 J21 J22 J23 J24 J25 J26
component class Designator: C11 C12 C13 C14 C15 C16 C17 C18 C19 C20 C21 C22 C23 C24 C25 C26 C27 C28 C30 C31 C32 C33 C34 C35 C36 C37 C38 C39 C40 C41 C42 C43 C46 C47 C49 C50 C51 C52 C53 C54 C185 C238 C239 C245 C246 C247 C248 C253 C255 D1 D2 D4 D10 D25 FB2 J27 L2 L3 L5 R7 R8 R9 R10 R11 R12 R13 R14 R15 R17 R20 R22 R24 R25 R26 R27 R28 R29 R30 R31 R32 R35 R37 R40 R41 R42 R43 R237 R328 R329 R330 R335 R337 TP1 TP9 TP11 TP15 TP16 TP17 TP21 U2 U3 U4 U5 U6 U7 U8 U25
component class Label: LBL1
component class AssemblyNote: ZZ1 ZZ2 ZZ3 ZZ4
component class FiducialMark: FID1 FID2 FID3 FID4 FID5 FID6

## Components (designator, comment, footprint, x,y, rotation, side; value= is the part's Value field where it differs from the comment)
C1 "CK45-B3FD222KYVNA" CK45_1250x600x1650 -249.636,77.54 r0 top value=2200pF
C2 "ALH82D161DD600" FP-ALH82D161DD600_RADIAL-MFG -18.55,103.15 r270 top value=160µF
C3 "ALH82D161DD600" FP-ALH82D161DD600_RADIAL-MFG -52.014,44.811 r210 top value=160µF
C4 "ALH82D161DD600" FP-ALH82D161DD600_RADIAL-MFG -18.525,29.35 r270 top value=160µF
C5 "ALH82D161DD600" FP-ALH82D161DD600_RADIAL-MFG -18.775,65.9 r270 top value=160µF
C6 "GRM1885C1H561JA01D" 0603 -224.558,109.366 r0 top value=560pF
C7 "GRM1885C1H201JA01D" 0603 -176.225,58.775 r90 top value=200pF
C8 "GRM1885C1H201JA01D" 0603 -176.2,55.35 r270 top value=200pF
C9 "GRM1885C1H201JA01D" 0603 -176.225,64.025 r270 top value=200pF
C10 "06033C104JAT2A" 0603 -243,114.5 r90 top value=0.1uF
C11 "TMK316AB7106KLHT" 1206_180 -91.05,95.7 r0 top value=10uF
C12 "GRM188R71C224KA01D" 0603 -86.9,98.675 r90 top value=0.22uF
C13 "C0603C331K5RACTU" 0603 -93.475,99.25 r270 top value=330pF
C14 "GRM188R71H221KA01D" 0603 -88.55,99.225 r270 top value=220pF
C15 "CGA4J3X7R1E225K125AB" 0805_HV -95.325,94.5 r0 top value=2.2uF
C16 "06033C104JAT2A" 0603 -117.275,104.225 r90 top value=0.1uF
C17 "TMK107BJ105KA-T" 0603 -115.575,104.225 r90 top value=1uF
C18 "GRMJN7R61C206ME05" 0704 -133.475,105.525 r90 top value=20uF
C19 "ZRB18AR61E106ME01L" FP-ZRB18AR61E106ME01L_0603-MFG -112.475,104.325 r90 top value=10µF
C20 "ZRB18AR61E106ME01L" FP-ZRB18AR61E106ME01L_0603-MFG -113.975,104.225 r270 top value=10µF
C21 "GRM1885C1H331JA01D" 0603 -117.375,109.325 r90 top value=330pF
C22 "06033C104JAT2A" 0603 -131.775,105.625 r270 top value=0.1uF
C23 "885012206089" 0603 -133.55,109 r270 top value=0.01uF
C24 "TMK316AB7106KLHT" 1206_180 -90.9,109.975 r0 top value=10uF
C25 "06033C104JAT2A" 0603 -86.7,113.525 r270 top value=0.1uF
C26 "C0603C331K5RACTU" 0603 -93.8,113.5 r270 top value=330pF
C27 "GRM188R71H221KA01D" 0603 -88.525,113.525 r270 top value=220pF
C28 "CGA4J3X7R1E225K125AB" 0805_HV -95.3,108.7 r0 top value=2.2uF
C29 "06033C104JAT2A" 0603 -171.25,93 r0 top value=0.1uF
C30 "C1812W104KDRACTU" 1812_254 -82.75,88.75 r0 top value=0.1uF
C31 "C1812W104KDRACTU" 1812_254 -81.25,96.75 r0 top value=0.1uF
C32 "GRM188R71H221KA01D" 0603 -117.875,113.9 r180 top value=220pF
C33 "GRM188R71H221KA01D" 0603 -117.875,115.3 r180 top value=220pF
C34 "GRM188R71H221KA01D" 0603 -117.875,116.7 r180 top value=220pF
C35 "GRM188R71H221KA01D" 0603 -117.875,118.2 r180 top value=220pF
C36 "GRM188R71H221KA01D" 0603 -199.2,91.05 r90 top value=220pF
C37 "GRM188R71H221KA01D" 0603 -202.997,91.126 r90 top value=220pF
C38 "06033C104JAT2A" 0603 -127.5,113.4 r270 top value=0.1uF
C39 "06033C104JAT2A" 0603 -121.1,113.5 r270 top value=0.1uF
C40 "UWT1E101MCL1GS" UWT_630x770 -99.7,118.2 r180 top value=100uF
C41 "GRM188R71H221KA01D" 0603 -130.25,118.525 r0 top value=220pF
C42 "GRM188R71H221KA01D" 0603 -130.25,120.225 r0 top value=220pF
C43 "06033C104JAT2A" 0603 -107.2,107.1 r0 top value=0.1uF
C44 "06033C104JAT2A" 0603 -64.015,91.396 r180 top value=0.1uF
C45 "GRM1885C1H561JA01D" 0603 -225.142,114.833 r270 top value=560pF
C46 "C1812W104KDRACTU" 1812_254 -82,92.75 r0 top value=0.1uF
C47 "06033C104JAT2A" 0603 -111.4,114.05 r0 top value=0.1uF
C48 "GRM188R71H221KA01D" 0603 -68.29,90.621 r0 top value=220pF
C49 "TMK316AB7106KLHT" 1206_180 -106.8,95.725 r0 top value=10uF
C50 "06033C104JAT2A" 0603 -103.025,98.8 r270 top value=0.1uF
C51 "C0603C331K5RACTU" 0603 -109.9,99.325 r270 top value=330pF
C52 "GRM188R71H221KA01D" 0603 -147.175,82.8 r0 top value=220pF
C53 "GRM188R71H221KA01D" 0603 -104.7,99.3 r270 top value=220pF
C54 "CGA4J3X7R1E225K125AB" 0805_HV -111.525,94.55 r0 top value=2.2uF
C55 "06033C104JAT2A" 0603 -158.6,88.05 r90 top value=0.1uF
C56 "GRM1885C1H561JA01D" 0603 -92.114,26.271 r270 top value=560pF
C57 "TMK316AB7106KLHT" 1206_180 -64.965,113.471 r180 top value=10uF
C58 "GRM188R71C224KA01D" 0603 -68.29,109.921 r270 top value=0.22uF
C59 "C0603C331K5RACTU" 0603 -61.49,109.721 r90 top value=330pF
C60 "GRM188R71H221KA01D" 0603 -66.59,109.921 r90 top value=220pF
C61 "CGA4J3X7R1E225K125AB" 0805_HV -60.315,114.346 r180 top value=2.2uF
C62 "06033C104JAT2A" 0603 -53.99,89.721 r180 top value=0.1uF
C63 "TMK107BJ105KA-T" 0603 -53.99,91.421 r180 top value=1uF
C64 "GRMJN7R61C206ME05" 0704 -55.315,73.921 r180 top value=20uF
C65 "ZRB18AR61E106ME01L" FP-ZRB18AR61E106ME01L_0603-MFG -54.04,92.871 r0 top value=10µF
C66 "GRM1885C1H331JA01D" 0603 -58.715,89.721 r180 top value=330pF
C67 "06033C104JAT2A" 0603 -55.29,75.471 r0 top value=0.1uF
C68 "885012206089" 0603 -58.565,74.071 r0 top value=0.01uF
C69 "TMK316AB7106KLHT" 1206_180 -65.04,99.171 r180 top value=10uF
C70 "06033C104JAT2A" 0603 -69.015,95.571 r90 top value=0.1uF
C71 "C0603C331K5RACTU" 0603 -62.39,95.521 r90 top value=330pF
C72 "GRM188R71H221KA01D" 0603 -67.365,95.571 r90 top value=220pF
C73 "CGA4J3X7R1E225K125AB" 0805_HV -60.465,99.646 r180 top value=2.2uF
C74 "GRM1885C1H561JA01D" 0603 -231.073,117.64 r180 top value=560pF
C75 "GRM1885C1H561JA01D" 0603 -228.476,105.153 r180 top value=560pF
C76 "C1812W104KDRACTU" 1812_254 -73.54,124.796 r180 top value=0.1uF
C77 "GRM188R71H221KA01D" 0603 -49.09,91.996 r0 top value=220pF
C78 "GRM188R71H221KA01D" 0603 -49.09,93.396 r0 top value=220pF
C79 "GRM188R71H221KA01D" 0603 -49.04,94.896 r0 top value=220pF
C80 "GRM188R71H221KA01D" 0603 -49.04,96.396 r0 top value=220pF
C81 "GRM1885C1H202JA01D" 0603 -97.662,25.438 r0 top value=2000pF
C82 "GRM188R71H221KA01D" 0603 -195.85,97.55 r180 top value=220pF
C83 "GRM188R71H221KA01D" 0603 -200.575,94.75 r90 top value=220pF
C84 "885012206095" 0603 -41.04,96.971 r180 top value=0.1uF
C85 "06033C104JAT2A" 0603 -45.5,97.5 r270 top value=0.1uF
C86 "GRM188R71H221KA01D" 0603 -40.54,85.471 r0 top value=220pF
C87 "GRM188R71H221KA01D" 0603 -40.49,88.921 r0 top value=220pF
C88 "C1812W104KDRACTU" 1812_254 -73.54,120.971 r180 top value=0.1uF
C89 "GRM188R71H221KA01D" 0603 -68.29,89.121 r0 top value=220pF
C90 "C1812W104KDRACTU" 1812_254 -73.54,116.971 r180 top value=0.1uF
C91 "06033C104JAT2A" 0603 -52.69,99.721 r90 top value=0.1uF
C92 "GRM188R71H221KA01D" 0603 -221,71.5 r180 top value=220pF
C93 "GRM188R71H221KA01D" 0603 -152.46,84.69 r0 top value=220pF
C94 "TMK316AB7106KLHT" 1206_180 -49.965,113.471 r180 top value=10uF
C95 "06033C104JAT2A" 0603 -53.765,110.296 r90 top value=0.1uF
C96 "GRM188R71H221KA01D" 0603 -47.015,110.096 r90 top value=220pF
C97 "GRM188R71H221KA01D" 0603 -52.115,109.971 r90 top value=220pF
C98 "GRM188R71H221KA01D" 0603 -153.025,90.85 r270 top value=220pF
C99 "CGA4J3X7R1E225K125AB" 0805_HV -45.59,114.496 r180 top value=2.2uF
C100 "GRM1885C1H202JA01D" 0603 -102.076,20.51 r180 top value=2000pF
C101 "GRM188R71H221KA01D" 0603 -149.6,90.05 r180 top value=220pF
C102 "R413F168050T0K" FP-R413F168050T0K_RADIAL-MFG -172.767,145.927 r90 top value=6.8nF
C103 "F862FY475K310ZV054" FP-F862FY475K310ZV054_RADIAL-MFG -77.669,154.042 r270 top value=4.7µF
C104 "F862FY475K310ZV054" FP-F862FY475K310ZV054_RADIAL-MFG -188.236,144.919 r270 top value=4.7µF
C105 "GRM188R72A104KA35J" 0603 -208.75,104.2 r270 top value=0.1uF
C106 "R413F168050T0K" FP-R413F168050T0K_RADIAL-MFG -81.86,174.879 r180 top value=6.8nF
C107 "GRM188R71H221KA01D" 0603 -217.975,98.175 r270 top value=220pF
C108 "GRM188R71H221KA01D" 0603 -181.2,71.6 r180 top value=220pF
C109 "GRM188R72A104KA35J" 0603 -189.677,111.051 r0 top value=0.1uF
C110 "885012206089" 0603 -189.675,109.175 r0 top value=0.01uF
C111 "TMK107BJ105KA-T" 0603 -189.69,107.263 r0 top value=1uF
C112 "GRM188R71H221KA01D" 0603 -219.698,94.872 r270 top value=220pF
C113 "GRM188R71H221KA01D" 0603 -178,74.2 r90 top value=220pF
C114 "06033C104JAT2A" 0603 -204.775,100.8 r270 top value=0.1uF
C115 "GRM188R72A104KA35J" 0603 -185.896,106.595 r180 top value=0.1uF
C116 "UVR1V100MDD1TA" CAPPR2-5x11 -60.344,3.864 r0 top value=10uF
C117 "06035A220JAT2A" 0603 -66.307,14.172 r0 top value=22pF
C118 "EEU-FR1E151B" FR_630X1120 -42.471,18.899 r90 top value=150uF
C119 "TMK107BJ105KA-T" 0603 -30.023,3.302 r270 top value=1uF
C120 "ZRB18AR61E106ME01L" FP-ZRB18AR61E106ME01L_0603-MFG -163.587,72.755 r0 top value=10µF
C121 "ZRB18AR61E106ME01L" FP-ZRB18AR61E106ME01L_0603-MFG -158.5,73.7 r270 top value=10µF
C122 "TMK107BJ105KA-T" 0603 -168.373,95.009 r270 top value=1uF
C123 "TMK107BJ105KA-T" 0603 -173.725,95.001 r90 top value=1uF
C124 "ZRB18AR61E106ME01L" FP-ZRB18AR61E106ME01L_0603-MFG -163.587,71.231 r0 top value=10µF
C125 "06033C104JAT2A" 0603 -160.03,73.771 r90 top value=0.1uF
C126 "ZRB18AR61E106ME01L" FP-ZRB18AR61E106ME01L_0603-MFG -159.23,80.121 r180 top value=10µF
C127 "06033C104JAT2A" 0603 -167.397,76.819 r0 top value=0.1uF
C128 "C0603X104K3RACTU" 0603 -102.071,18.532 r0 top value=0.1uF
C129 "C0603C101J5GAC" 0603 -188,99.5 r180 top value=100pF
C130 "GRM188R71H221KA01D" 0603 -186.775,71.075 r180 top value=220pF
C131 "GRM188R71H221KA01D" 0603 -179.975,74.125 r90 top value=220pF
C132 "GRM188R71H221KA01D" 0603 -214.8,91.225 r90 top value=220pF
C133 "GRM188R71H221KA01D" 0603 -225.565,91.139 r90 top value=220pF
C134 "GRM188R71H221KA01D" 0603 -214.099,94.87 r90 top value=220pF
C135 "GRM188R71H221KA01D" 0603 -183.9,70.3 r90 top value=220pF
C136 "GRM188R71H221KA01D" 0603 -194.3,71 r0 top value=220pF
C137 "GRM188R71H221KA01D" 0603 -190.375,71.025 r0 top value=220pF
C138 "C0603C101J5GAC" 0603 -178.2,78 r0 top value=100pF
C141 "C0603X104K3RACTU" 0603 -175.395,61.512 r180 top value=0.1uF
C142 "C0603X104K3RACTU" 0603 -215.896,61.65 r0 top value=0.1uF
C143 "GRM1885C1H201JA01D" 0603 -215.896,63.682 r0 top value=200pF
C144 "GRM1885C1H201JA01D" 0603 -176.225,67.35 r90 top value=200pF
C145 "GRM188R71H221KA01D" 0603 -216.896,74.129 r270 top value=220pF
C146 "C0603C561J5GACTU" 0603 -223.25,97.875 r180 top value=560pF
C148 "GRM1885C1H201JA01D" 0603 -215.101,66.476 r90 top value=200pF
C150 "GRM1885C1H202JA01D" 0603 -215.934,59.618 r180 top value=2000pF
C151 "GRM188R71H221KA01D" 0603 -211.375,74.116 r270 top value=220pF
C152 "GRM188R71H221KA01D" 0603 -221.725,77.9 r270 top value=220pF
C154 "GRM1885C1H202JA01D" 0603 -214.88,57.078 r270 top value=2000pF
C155 "GRM1885C1H201JA01D" 0603 -203.499,60.78 r270 top value=200pF
C156 "GRM1885C1H202JA01D" 0603 -187.705,63.981 r90 top value=2000pF
C157 "GRM188R71H221KA01D" 0603 -216.363,77.901 r270 top value=220pF
C158 "C0603C561J5GACTU" 0603 -218.675,74.125 r270 top value=560pF
C159 "GRM1885C1H202JA01D" 0603 -187.705,67.537 r90 top value=2000pF
C160 "GRM1885C1H201JA01D" 0603 -203.499,57.478 r270 top value=200pF
C161 "C0603X104K3RACTU" 0603 -199.181,67.13 r0 top value=0.1uF
C162 "GRM1885C1H202JA01D" 0603 -187.738,60.467 r90 top value=2000pF
C163 "GRM188R71H221KA01D" 0603 -202.737,63.32 r180 top value=220pF
C164 "GRM188R71H221KA01D" 0603 -210.013,77.901 r270 top value=220pF
C165 "C0603X104K3RACTU" 0603 -206.918,67.871 r0 top value=0.1uF
C166 "GRM1885C1H202JA01D" 0603 -187.738,56.873 r270 top value=2000pF
C167 "GRM188R71H221KA01D" 0603 -128.15,92.575 r180 top value=220pF
C168 "GRM188R71H221KA01D" 0603 -128.125,90.975 r180 top value=220pF
C169 "06033C104JAT2A" 0603 -138.55,88.075 r180 top value=0.1uF
C170 "GRM188R71H221KA01D" 0603 -128.1,89.375 r180 top value=220pF
C171 "GRM188R71H221KA01D" 0603 -132.55,88.05 r0 top value=220pF
C172 "GRM188R71H221KA01D" 0603 -140.875,89.725 r0 top value=220pF
C173 "GRM188R71H221KA01D" 0603 -140.7,92.2 r90 top value=220pF
C174 "GRM188R71H221KA01D" 0603 -128.425,84.675 r180 top value=220pF
C175 "GRM188R71H221KA01D" 0603 -128.4,83.075 r180 top value=220pF
C176 "06033C104JAT2A" 0603 -138.225,79.875 r180 top value=0.1uF
C177 "GRM188R71H221KA01D" 0603 -128.4,81.45 r180 top value=220pF
C178 "GRM188R71H221KA01D" 0603 -130.775,79.75 r180 top value=220pF
C179 "GRM188R71H221KA01D" 0603 -140.725,81.575 r0 top value=220pF
C180 "GRM188R71H221KA01D" 0603 -140.725,83.175 r0 top value=220pF
C181 "TMK107BJ105KA-T" 0603 -179.05,91.026 r270 top value=1uF
C182 "06033C104JAT2A" 0603 -180.828,91.026 r90 top value=0.1uF
C185 "06033C104JAT2A" 0603 -120.95,91.675 r0 top value=0.1uF
C186 "06033C104JAT2A" 0603 -36.59,119.821 r180 top value=0.1uF
C188 "ZRB18AR61E106ME01L" FP-ZRB18AR61E106ME01L_0603-MFG -54.098,94.579 r0 top value=10µF
C189 "TMK107BJ105KA-T" 0603 -240.873,105.19 r270 top value=1uF
C190 "GRM188R71H221KA01D" 0603 -140.667,71.747 r0 top value=220pF
C191 "GRM21BR6YA106KE43L" 0805_HV -238.333,105.19 r90 top value=10uF
C192 "GRM188R71H221KA01D" 0603 -163.375,108.725 r0 top value=220pF
C193 "GRM188R71H221KA01D" 0603 -140.667,67.937 r0 top value=220pF
C194 "GRM188R71H221KA01D" 0603 -163.375,105.169 r0 top value=220pF
C195 "CL05B104KO5NNNC" 0402 -242.916,105.08 r90 top value=0.1uF
C196 "GRM188R71H221KA01D" 0603 -163.375,101.613 r0 top value=220pF
C197 "CL05B104KO5NNNC" 0402 -242.916,94.92 r90 top value=0.1uF
C198 "TMK107BJ105KA-T" 0603 -260.676,92.873 r90 top value=1uF
C199 "GRM188R71H221KA01D" 0603 -140.667,64.127 r0 top value=220pF
C200 "GRM188R71H221KA01D" 0603 -150.553,100.604 r180 top value=220pF
C201 "06033C104JAT2A" 0603 -153.971,111.925 r270 top value=0.1uF
C202 "GRM188R71H221KA01D" 0603 -128.945,62.618 r180 top value=220pF
C203 "06033C104JAT2A" 0603 -132.793,73.504 r180 top value=0.1uF
C204 "GRM188R71H221KA01D" 0603 -150.553,104.487 r180 top value=220pF
C205 "CL05B104KO5NNNC" 0402 -257.394,93.396 r270 top value=0.1uF
C206 "GRM188R71H221KA01D" 0603 -150.553,108.37 r180 top value=220pF
C207 "GRM21BR6YA106KE43L" 0805_HV -262.988,92.38 r270 top value=10uF
C208 "GRM188R71H221KA01D" 0603 -128.983,66.38 r180 top value=220pF
C209 "GRM188R71H221KA01D" 0603 -128.983,69.936 r180 top value=220pF
C210 "TMK107BJ105KA-T" 0603 -259.437,105.199 r270 top value=1uF
C211 "TMK107BJ105KA-T" 0603 -264.506,108.685 r90 top value=1uF
C212 "0402B103K500CT" 0402 -257.394,105.08 r90 top value=0.01uF
C213 "GRM21BR6YA106KE43L" 0805_HV -261.723,105.199 r90 top value=10uF
C214 "TMK107BJ105KA-T" 0603 -240.615,66.074 r270 top value=1uF
C215 "GRM21BR6YA106KE43L" 0805_HV -238.075,66.328 r90 top value=10uF
C216 "CL05B104KO5NNNC" 0402 -242.658,65.964 r90 top value=0.1uF
C217 "GRM1885C1H470JA01D" 0603 -263.857,95.649 r180 top value=47pF
C218 "GRM188R71H221KA01D" 0603 -241.9,97.169 r180 top value=220pF
C219 "GRM188R71H221KA01D" 0603 -241.9,99.234 r180 top value=220pF
C220 "C0603X472K5RACTU" 0603 -261.247,96.549 r90 top value=4700pF
C221 "GRM1885C1H470JA01D" 0603 -263.819,97.427 r0 top value=47pF
C222 "CL05B104KO5NNNC" 0402 -242.658,54.534 r270 top value=0.1uF
C223 "TMK107BJ105KA-T" 0603 -259.7,61.1 r270 top value=1uF
C224 "CL05B104KO5NNNC" 0402 -257.1,61.1 r90 top value=0.1uF
C225 "GRM21BR6YA106KE43L" 0805_HV -261.9,61.616 r90 top value=10uF
C226 "TMK107BJ105KA-T" 0603 -259.179,67.234 r90 top value=1uF
C227 "0402B103K500CT" 0402 -257.136,67.234 r270 top value=0.01uF
C228 "GRM21BR6YA106KE43L" 0805_HV -261.719,67.877 r270 top value=10uF
C229 "C1812W104KDRACTU" 1812_254 -62.721,26.259 r0 top value=0.1uF
C230 "C0603X104K3RACTU" 0603 -233.778,114.668 r90 top value=0.1uF
C231 "GRM188R71H221KA01D" 0603 -181.9,74.125 r90 top value=220pF
C232 "GRM188R71H221KA01D" 0603 -237.79,58.819 r180 top value=220pF
C233 "GRM1885C1H470JA01D" 0603 -263.778,56.566 r180 top value=47pF
C234 "GRM188R71H221KA01D" 0603 -237.79,60.597 r180 top value=220pF
C235 "GRM188R71H221KA01D" 0603 -237.79,57.041 r180 top value=220pF
C236 "C0603X472K5RACTU" 0603 -260.946,57.582 r90 top value=4700pF
C237 "GRM1885C1H470JA01D" 0603 -263.778,58.344 r0 top value=47pF
C238 "UWT1E101MCL1GS" UWT_630x770 -118.9,87.35 r180 top value=100uF
C239 "UWT1E101MCL1GS" UWT_630x770 -118.9,80 r180 top value=100uF
C240 "UWT1E101MCL1GS" UWT_630x770 -48.49,102.821 r0 top value=100uF
C241 "C4AKOBU4500A31J" FP-C4AKOBU4500A31J_RADIAL-MFG -83.75,49.75 r270 top value=5µF
C242 "C4AKOBU4500A31J" FP-C4AKOBU4500A31J_RADIAL-MFG -80.75,76.75 r180 top value=5µF
C243 "DE6E3KJ222MN3A" E_900x700x900 -6.448,137.084 r180 top value=2200pF
C244 "DE6E3KJ222MN3A" E_900x700x900 -6.905,163.627 r0 top value=2200pF
C245 "GRM188R71H221KA01D" 0603 -102.8,108.5 r180 top value=220pF
C246 "GRM188R71H221KA01D" 0603 -102.8,110 r180 top value=220pF
C247 "GRM188R71H221KA01D" 0603 -107.017,115.798 r180 top value=220pF
C248 "GRM188R71H221KA01D" 0603 -107,117.525 r180 top value=220pF
C249 "GRM188R71H221KA01D" 0603 -55.19,104.221 r270 top value=220pF
C250 "GRM188R71H221KA01D" 0603 -56.69,104.221 r270 top value=220pF
C251 "UWT1E101MCL1GS" UWT_630x770 -49.89,71.121 r90 top value=100uF
C252 "UWT1E101MCL1GS" UWT_630x770 -42.89,77.721 r180 top value=100uF
C253 "GRM188R71H221KA01D" 0603 -116.35,93.125 r180 top value=220pF
C254 "GRM188R71H221KA01D" 0603 -40.99,118.121 r0 top value=220pF
C255 "GRM188R71H221KA01D" 0603 -116.362,94.604 r180 top value=220pF
C256 "GRM188R71H221KA01D" 0603 -41.019,116.729 r0 top value=220pF
D1 "GB02SLT12-214" FP-GB02SLT12-214_DO-214AA-MFG -100.875,91.225 r180 top
D2 "BZT52C16-7-F" SOD-123 -91.9,117.9 r0 top value=16V
D4 "KG DELLS1.22-JGKH-24" "FP-KG DELLS1.22-JGKH-24_0603-MFG" -95.3,99.9 r90 top
D7 "GB02SLT12-214" FP-GB02SLT12-214_DO-214AA-MFG -56,119 r0 top
D8 "BZT52C16-7-F" SOD-123 -65.14,115.971 r180 top value=16V
D10 "KG DELLS1.22-JGKH-24" "FP-KG DELLS1.22-JGKH-24_0603-MFG" -98.7,111.2 r90 top
D13 "B160-13-F" SMA -206.75,108.25 r0 top value=60V
D14 "1N4148W-7-F" SOD-123 -65.609,8.399 r180 top value=100V
D15 "ES1JAF" SMAF -69.698,3.632 r270 top value=600V
D16 "KG DELLS1.22-JGKH-24" "FP-KG DELLS1.22-JGKH-24_0603-MFG" -26.972,2.399 r180 top
D17 "KG DELLS1.22-JGKH-24" "FP-KG DELLS1.22-JGKH-24_0603-MFG" -153.7,79.5 r270 top
D18 "KG DELLS1.22-JGKH-24" "FP-KG DELLS1.22-JGKH-24_0603-MFG" -146.117,79.807 r90 top
D19 "BZT52C16-7-F" SOD-123 -44.471,23.899 r180 top value=16V
D20 "RS3K-E3/9AT" SMC -50.471,19.674 r90 top value=800V
D23 "KG DELLS1.22-JGKH-24" "FP-KG DELLS1.22-JGKH-24_0603-MFG" -170.5,76.2 r90 top
D24 "KG DELLS1.22-JGKH-24" "FP-KG DELLS1.22-JGKH-24_0603-MFG" -167.5,89.5 r180 top
D25 "KG DELLS1.22-JGKH-24" "FP-KG DELLS1.22-JGKH-24_0603-MFG" -124.4,90.3 r270 top
D26 "KG DELLS1.22-JGKH-24" "FP-KG DELLS1.22-JGKH-24_0603-MFG" -59.09,116.171 r0 top
D27 "KG DELLS1.22-JGKH-24" "FP-KG DELLS1.22-JGKH-24_0603-MFG" -60.54,101.721 r180 top
D28 "KG DELLS1.22-JGKH-24" "FP-KG DELLS1.22-JGKH-24_0603-MFG" -45.16,116.221 r180 top
F1 "SF-3812F2500T-2" FP-SF-3812F2500T-2_SMD2-MFG -256.425,145.5 r180 top
F2 "SF-3812F2500T-2" FP-SF-3812F2500T-2_SMD2-MFG -256.45,130.025 r180 top
FB2 "MH1608-601Y" FP-MH1608-601Y_0603-MFG -135.375,105.725 r90 top
FB4 "MH1608-601Y" FP-MH1608-601Y_0603-MFG -55.29,71.971 r180 top
FB6 "MH1608-601Y" FP-MH1608-601Y_0603-MFG -189.75,105.4 r180 top
FB7 "MH1608-601Y" FP-MH1608-601Y_0603-MFG -172.126,61.554 r180 top
FB8 "MH1608-601Y" FP-MH1608-601Y_0603-MFG -219.05,61.7 r0 top
FB9 "MH1608-601Y" FP-MH1608-601Y_0603-MFG -176.51,90.264 r180 top
FB11 "MH1608-601Y" FP-MH1608-601Y_0603-MFG -156.725,87.425 r90 top
FB12 "MH1608-601Y" FP-MH1608-601Y_0603-MFG -101.952,17.069 r0 top
FB14 "MH1608-601Y" FP-MH1608-601Y_0603-MFG -236.023,115.033 r90 top
FB18 "BLM15EX331SN1D" FP-BLM15EX331SN1D_0402-MFG -264.252,106.371 r180 top
FB23 "BLM15EX331SN1D" FP-BLM15EX331SN1D_0402-MFG -263.75,66.25 r90 top
FID1 "Fiducial" Fiducial10-20 -244.903,154.508 r0 top
FID2 "Fiducial" Fiducial10-20 -261.5,52.5 r0 top
FID3 "Fiducial" Fiducial10-20 -17.272,1.854 r0 top
FID4 "Fiducial" Fiducial10-20 -49.5,150.5 r180 bottom
FID5 "Fiducial" Fiducial10-20 -2.866,118.745 r180 bottom
FID6 "Fiducial" Fiducial10-20 -2.743,15.062 r180 bottom
J1 "FCR7350L" FP-FCR7350L_CONN_BANANA_JACK-MFG -281.275,130.1 r0 top
J2 "FCR7350G" FP-FCR7350G_CONN_BANANA_JACK-MFG -281.325,161.725 r0 top
J3 "FCR7350B" FP-FCR7350B_CONN_BANANA_JACK-MFG -178.482,182.372 r270 top
J4 "61300211121" WURTH_61300211121 -175,103.025 r180 top
J5 "61300211121" WURTH_61300211121 -140.179,101.5 r180 top
J6 "694106402002" FP-694106402002_CONN_PWR_10MM7_9MM0-MFG -113.7,56.3 r0 top
J7 "61300211121" WURTH_61300211121 -67.921,28.3 r270 top
J8 "SSM-107-L-SV-BE" FP-SSM-107-L-SV-BE_HDR7-MFG -158.9,64.503 r180 top
J9 "FCR7350B" FP-FCR7350B_CONN_BANANA_JACK-MFG -281.4,146.005 r0 top
J10 "SHF-112-01-L-D-TH" FP-SHF-112-01-L-D-TH_HDR24-MFG -159,55 r180 top
J11 "HSEC8-160-01-L-DV-A-BL" controlCARD-120HSEC -204.45,84.676 r0 top
J12 "SHF-112-01-L-D-TH" FP-SHF-112-01-L-D-TH_HDR24-MFG -135,55 r180 top
J13 "61300211121" WURTH_61300211121 -140.179,98.222 r180 top
J14 "61300211121" WURTH_61300211121 -175,106.3 r180 top
J15 "618009231121" Wurth_618009231121 -279.919,99.608 r180 top
J16 "61300211121" WURTH_61300211121 -257.6,83.5 r0 top
J17 "618009231121" Wurth_618009231121 -280.025,67 r180 top
J18 "74650073R" Wurth_WP-THRBU -97.151,5.563 r0 top
J19 "74650073R" Wurth_WP-THRBU -79.854,5.69 r0 top
J20 "61300211121" WURTH_61300211121 -175,109.5 r180 top
J21 "61300211121" WURTH_61300211121 -160.913,95.479 r270 top
J22 "61300211121" WURTH_61300211121 -164.055,95.479 r270 top
J23 "61300211121" WURTH_61300211121 -157.721,95.479 r270 top
J24 "61300211121" WURTH_61300211121 -154.579,95.479 r270 top
J25 "61300211121" WURTH_61300211121 -151.311,95.479 r270 top
J26 "61300211121" WURTH_61300211121 -148.093,95.479 r270 top
J27 "PK007-015" FP-PK007-015_CONN_TESTCLIP-MFG -84.654,120.853 r0 top
J31 "FCR7350G" FP-FCR7350G_CONN_BANANA_JACK-MFG -150.948,182.448 r270 top
J32 "FCR7350L" FP-FCR7350L_CONN_BANANA_JACK-MFG -164.639,182.425 r270 top
K1 "G5PZ-1A-E DC12" "FP-G5PZ-1A-E DC12_PTH_RELAY_23MM8_10MM3-MFG" -206.803,132.613 r90 top
K2 "G5PZ-1A-E DC12" "FP-G5PZ-1A-E DC12_PTH_RELAY_23MM8_10MM3-MFG" -198.091,171.933 r180 top
L1 "145453" FP-145453_PTH12-MFG -117.21,149.423 r270 top value=87uH
L2 "SDEM20161T-4R7MS" FP-SDEM20161T-4R7MS_SMD2-MFG -96.9,97.4 r270 top
L3 "SDEM20161T-4R7MS" FP-SDEM20161T-4R7MS_SMD2-MFG -96.45,111.6 r270 top
L4 "145453" FP-145453_PTH12-MFG -39.003,152.075 r90 top value=87uH
L5 "SDEM20161T-4R7MS" FP-SDEM20161T-4R7MS_SMD2-MFG -112.825,97.4 r270 top
L6 "SDEM20161T-4R7MS" FP-SDEM20161T-4R7MS_SMD2-MFG -58.89,111.821 r90 top
L7 "SDEM20161T-4R7MS" FP-SDEM20161T-4R7MS_SMD2-MFG -59.04,97.021 r90 top
L8 "BLM18HE152SN1D" 0603 -235.042,104.064 r180 top value="1500 ohm"
L9 "SDEM20161T-4R7MS" FP-SDEM20161T-4R7MS_SMD2-MFG -44.79,112.221 r0 top
L10 "047708" FP-047708_PTH4-MFG -156.043,144.405 r90 top
L11 "047708" FP-047708_PTH4-MFG -230.704,158.801 r270 top
L12 "BLM18HE152SN1D" 0603 -238.598,94.412 r180 top value="1500 ohm"
L13 "MS0311" FP-MS0311_SMT_IND_12MM0_12MM0-MFG -40.671,6.799 r0 top value=220uH
L14 "SRN3015-100M" SRN3015 -167.766,73.881 r270 top value=10uH
L16 "BLM18HE152SN1D" 0603 -234.519,65.058 r180 top value="1500 ohm"
L17 "BLM18HE152SN1D" 0603 -239.356,55.033 r180 top value="1500 ohm"
L25 "ACT45B-101-2P-TL003" FP-ACT45B-101-2P-TL003_SMT_4MM5_3MM2-MFG -263.525,86 r270 top
L31 "ACT45B-101-2P-TL003" FP-ACT45B-101-2P-TL003_SMT_4MM5_3MM2-MFG -259.6,71.9 r180 top
LBL1 "THT-14-423-10" Label_650x200 -100.5,41.25 r90 top
LOGO1 "CAUTION HOT SURFACE" IEC_HotSurface_Small -107.972,65.659 r0 top
LOGO2 "DANGER HIGH VOLTAGE" IEC_HighVoltage_Small -17.903,6.071 r0 top
Logo3 "CE Mark" CE_Mark_5mm -102.75,59 r0 top
Logo5 "FCC disclaimer" FCC_disclaimer 30.5,48.5 r270 bottom
Logo6 "WEEE logo" WEEE_Minimum -101.25,68.5 r0 top
MP1 "9774015960R" FP-9774015960R_ROUND_SPACER_6MM0-MFG#1 -272,175 r180 bottom
MP2 "9774015960R" FP-9774015960R_ROUND_SPACER_6MM0-MFG#1 -70,175 r180 bottom
MP3 "9774015960R" FP-9774015960R_ROUND_SPACER_6MM0-MFG#2 -85,132 r180 bottom
MP4 "9774015960R" FP-9774015960R_ROUND_SPACER_6MM0-MFG#1 -5,175 r180 bottom
MP5 "9774015960R" FP-9774015960R_ROUND_SPACER_6MM0-MFG#2 -5,5 r180 bottom
MP6 "9774015960R" FP-9774015960R_ROUND_SPACER_6MM0-MFG#2 -5,126 r180 bottom
MP7 "9774015960R" FP-9774015960R_ROUND_SPACER_6MM0-MFG#2 -5,84 r180 bottom
MP8 "9774015960R" FP-9774015960R_ROUND_SPACER_6MM0-MFG#2 -107,75 r180 bottom
MP12 "9774015960R" FP-9774015960R_ROUND_SPACER_6MM0-MFG#2 -247,86 r180 bottom
Q1 "CSD17318Q2" FP-CSD17318Q2_WSON6-MFG -205,104.25 r90 top
Q2 "STD3NK80ZT4" DPAK -63.068,19.583 r180 top value=800V
R1 "RG1608P-560-B-T5" 0603 -94.775,17.575 r180 top value=56
R2 "RT0603BRD077K32L" 0603 -174.475,58.75 r270 top value=7.32k
R3 "RT0603BRD077K32L" 0603 -172.775,58.75 r90 top value=7.32k
R4 "RT0603BRD077K32L" 0603 -172.75,55.425 r90 top value=7.32k
R5 "RG1608P-103-B-T5" 0603 -243,111 r270 top value=10.0k
R6 "TMP6131LPGM" LPG0002A-MFG -245.29,114 r90 top value=10kΩ
R7 "CRCW12064R70JNEAHP" 1206 -105.75,92.175 r270 top value=4.7
R8 "RG1608P-560-B-T5" 0603 -117.875,121 r0 top value=56
R9 "RG1608P-560-B-T5" 0603 -117.875,119.6 r0 top value=56
R10 "RG1608P-563-B-T5" 0603 -90.2,99.225 r270 top value=56.0k
R11 "ERJ-3EKF1202V" 0603 -131.725,110.3 r270 top value=12.0k
R12 "RT0603DRE0738K8L" 0603 -115.675,107.625 r90 top value=38.8k
R13 "ERJ-3EKF1202V" 0603 -137.175,106.025 r90 top value=12.0k
R14 "RC0603FR-073K01L" 0603 -138.875,106.025 r90 top value=3.01k
R15 "RG1608P-103-B-T5" 0603 -114.875,110.125 r180 top value=10.0k
R16 "CRCW06032K70JNEA" 0603 -170,97.5 r0 top value=2.7k
R17 "RC0603JR-075K6L" 0603 -96.8,100.2 r90 top value=5.6k
R18 "RG1608P-560-B-T5" 0603 -45.965,89.096 r180 top value=56
R19 "RG1608P-560-B-T5" 0603 -49.09,90.596 r180 top value=56
R20 "RCS06030000Z0EA" 0603 -133.95,120.125 r0 top value=0
R21 "RCS06030000Z0EA" 0603 -163.331,110.668 r180 top value=0
R22 "RCS06030000Z0EA" 0603 -133.95,118.425 r0 top value=0
R23 "RG1608P-103-B-T5" 0603 -224.481,107.424 r0 top value=10.0k
R24 "RG1608P-560-B-T5" 0603 -131.525,116.475 r0 top value=56
R25 "RG1608P-560-B-T5" 0603 -92,113.5 r270 top value=56
R26 "RG1608P-560-B-T5" 0603 -131.55,115.075 r0 top value=56
R27 "RG1608P-560-B-T5" 0603 -91.85,99.225 r270 top value=56
R28 "RG1608P-560-B-T5" 0603 -134.9,114.125 r0 top value=56
R29 "RG1608P-560-B-T5" 0603 -113.8,116.95 r90 top value=56
R30 "RG1608P-563-B-T5" 0603 -90.25,113.525 r270 top value=56.0k
R31 "RG1608P-560-B-T5" 0603 -134.9,112.6 r0 top value=56
R32 "RG1608P-560-B-T5" 0603 -109.7,110 r90 top value=56
R33 "RG1608P-103-B-T5" 0603 -68.29,92.021 r0 top value=10.0k
R34 "RG1608P-103-B-T5" 0603 -68.29,87.621 r0 top value=10.0k
R35 "RG1608P-560-B-T5" 0603 -111.575,100.025 r270 top value=56
R36 "RG1608P-103-B-T5" 0603 -223.2,114.897 r270 top value=10.0k
R37 "RG1608P-560-B-T5" 0603 -108.15,99.3 r270 top value=56
R38 "RG1608P-560-B-T5" 0603 -149.05,84.65 r180 top value=56
R39 "RG1608P-560-B-T5" 0603 -155.921,84.966 r180 top value=56
R40 "RG1608P-563-B-T5" 0603 -106.4,99.3 r270 top value=56.0k
R41 "CRCW12064R70JNEAHP" 1206 -108.2,92.175 r270 top value=4.7
R42 "RC0603JR-075K6L" 0603 -97.1,113.6 r180 top value=5.6k
R43 "RC0603JR-075K6L" 0603 -124.4,87.6 r90 top value=5.6k
R44 "RG1608P-563-B-T5" 0603 -64.89,109.721 r90 top value=56.0k
R45 "RT0603DRE0738K8L" 0603 -57.29,91.471 r180 top value=38.8k
R46 "ERJ-3EKF1202V" 0603 -55.29,70.221 r180 top value=12.0k
R47 "ERJ-3EKF1202V" 0603 -59.79,75.746 r0 top value=12.0k
R48 "RC0603FR-073K01L" 0603 -55.29,68.721 r180 top value=3.01k
R49 "RG1608P-103-B-T5" 0603 -59.79,92.221 r270 top value=10.0k
R50 "RG1608P-103-B-T5" 0603 -240.25,92 r0 top value=10.0k
R51 "RC0603JR-075K6L" 0603 -57.19,114.921 r90 top value=5.6k
R52 "RC0603JR-075K6L" 0603 -63.29,101.721 r0 top value=5.6k
R53 "CRCW12064R70JNEAHP" 1206 -50.09,116.196 r180 top value=4.7
R54 "RCS06030000Z0EA" 0603 -40.49,87.221 r0 top value=0
R55 "CRCW12064R70JNEAHP" 1206 -49.5,119 r180 top value=4.7
R56 "RCS06030000Z0EA" 0603 -40.59,83.721 r0 top value=0
R57 "RCS06030000Z0EA" 0603 -194.8,74.1 r90 top value=0
R58 "RG1608P-560-B-T5" 0603 -37.84,82.446 r90 top value=56
R59 "RG1608P-560-B-T5" 0603 -64.09,95.521 r90 top value=56
R60 "RG1608P-563-B-T5" 0603 -65.79,95.546 r90 top value=56.0k
R61 "RG1608P-560-B-T5" 0603 -37.04,85.721 r90 top value=56
R62 "RG1608P-560-B-T5" 0603 -63.19,109.721 r90 top value=56
R63 "RG1608P-560-B-T5" 0603 -36.04,82.471 r90 top value=56
R64 "RG1608P-560-B-T5" 0603 -61.54,88.421 r270 top value=56
R65 "RG1608P-560-B-T5" 0603 -34.79,85.721 r90 top value=56
R66 "RG1608P-560-B-T5" 0603 -55.29,97.221 r180 top value=56
R67 "RCS06030000Z0EA" 0603 -222.119,74.028 r270 top value=0
R68 "RG1608P-103-B-T5" 0603 -90.171,26.281 r90 top value=10.0k
R69 "RG1608P-560-B-T5" 0603 -44.29,109.221 r180 top value=56
R70 "RC0603JR-07680RL" 0603 -172.2,75.9 r270 top value=680
R71 "RG1608P-560-B-T5" 0603 -48.69,109.596 r90 top value=56
R72 "RG1608P-560-B-T5" 0603 -146.1,89.1 r180 top value=56
R73 "RG1608P-560-B-T5" 0603 -155.975,89.5 r180 top value=56
R74 "RG1608P-563-B-T5" 0603 -50.415,109.596 r90 top value=56.0k
R75 "PTCEL13R600LBE" FP-PTCEL13R600LBE_RADIAL-MFG -207.844,151.79 r0 top value=60Ω
R76 "RC0603JR-07680RL" 0603 -163.579,89.5 r180 top value=680
R77 "ERJ-8ENF1693V" 1206 -4.155,145.066 r270 top value=169k
R78 "IsoM5-275-B-L2" FP-IsoM5-275-B-L2_RADIAL-MFG -256.485,170.088 r270 top
R79 "ERJ-8ENF1693V" 1206 -7.108,144.992 r270 top value=169k
R80 "ERJ-8ENF1693V" 1206 -10.156,145.066 r270 top value=169k
R81 "IsoM5-275-B-L2" FP-IsoM5-275-B-L2_RADIAL-MFG -248.053,170.078 r270 top
R82 "IsoM5-275-B-L2" FP-IsoM5-275-B-L2_RADIAL-MFG -235.496,134.01 r180 top
R83 "RG1608P-560-B-T5" 0603 -194.156,110.165 r270 top value=56
R84 "RG1608P-103-B-T5" 0603 -199.978,110.279 r90 top value=10.0k
R85 "RG1608P-103-B-T5" 0603 -193.108,105.34 r180 top value=10.0k
R86 "RG1608P-560-B-T5" 0603 -196.095,110.203 r90 top value=56
R87 "RG1608P-560-B-T5" 0603 -192.25,110.175 r270 top value=56
R88 "RG1608P-560-B-T5" 0603 -198.039,110.279 r270 top value=56
R89 "RT0603DRE07200RL" 0603 -201.5,100.8 r90 top value=200
R90 "RG1608P-103-B-T5" 0603 -203.125,100.8 r270 top value=10.0k
R91 "RT0603BRD0748K1L" 0603 -185.896,108.373 r180 top value=48.1k
R92 "RT0603DRE075K76L" 0603 -185.896,110.151 r0 top value=5.76k
R93 "RG1608P-333-B-T5" 0603 -66.471,11.399 r90 top value=33.0k
R94 "CRCW1206475KFKEA" 1206 -66.53,3.232 r270 top value=475k
R95 "RT0603DRE0715K6L" 0603 -64.471,11.399 r270 top value=15.6k
R96 "RT0603DRE07301RL" 0603 -55.621,12.899 r270 top value=301
R97 "RT0603BRD077K32L" 0603 -174.45,55.375 r90 top value=7.32k
R98 "ERJ-6RSFR10V" 0805_HV -53.121,9.924 r0 top value=0.1
R99 "RG1608P-103-B-T5" 0603 -259.2,100.75 r0 top value=10.0k
R100 "RC0603JR-075K6L" 0603 -25.984,5.22 r90 top value=5.6k
R101 "ERJ-3GEYJ152V" 0603 -151.9,79.8 r90 top value=1.5k
R102 "RC0603JR-07680RL" 0603 -147.8,79.875 r270 top value=680
R103 "RT0603BRD07105KL" 0603 -158.252,77.327 r270 top value=105k
R104 "RG1608P-103-B-T5" 0603 -163.625,78.7 r180 top value=10.0k
R105 "RG1608P-103-B-T5" 0603 -166.6,95 r90 top value=10.0k
R106 "RT0603DRE0720KL" 0603 -160.03,77.327 r90 top value=20.0k
R107 "CRCW06031K50JNEA" 0603 -167.397,78.597 r0 top value=1.5k
R108 "TNPV1206560KBEEN" TNPV1206 -90.4,12.8 r90 top value=560k
R109 "TNPV1206560KBEEN" TNPV1206 -87.4,15.9 r90 top value=560k
R110 "TNPV1206560KBEEN" TNPV1206 -87.4,21.3 r90 top value=560k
